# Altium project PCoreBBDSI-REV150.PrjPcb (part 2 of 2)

## Sheet 07) LCD CAM.SchDoc: LCD / CAM
size A3; Origin: Eagle; DrawnBy: T.Minas; DocumentNumber: 7; Revision: 1.50; SheetNumber: 7; SheetTotal: 10; Project: PicoCoreBBDSI
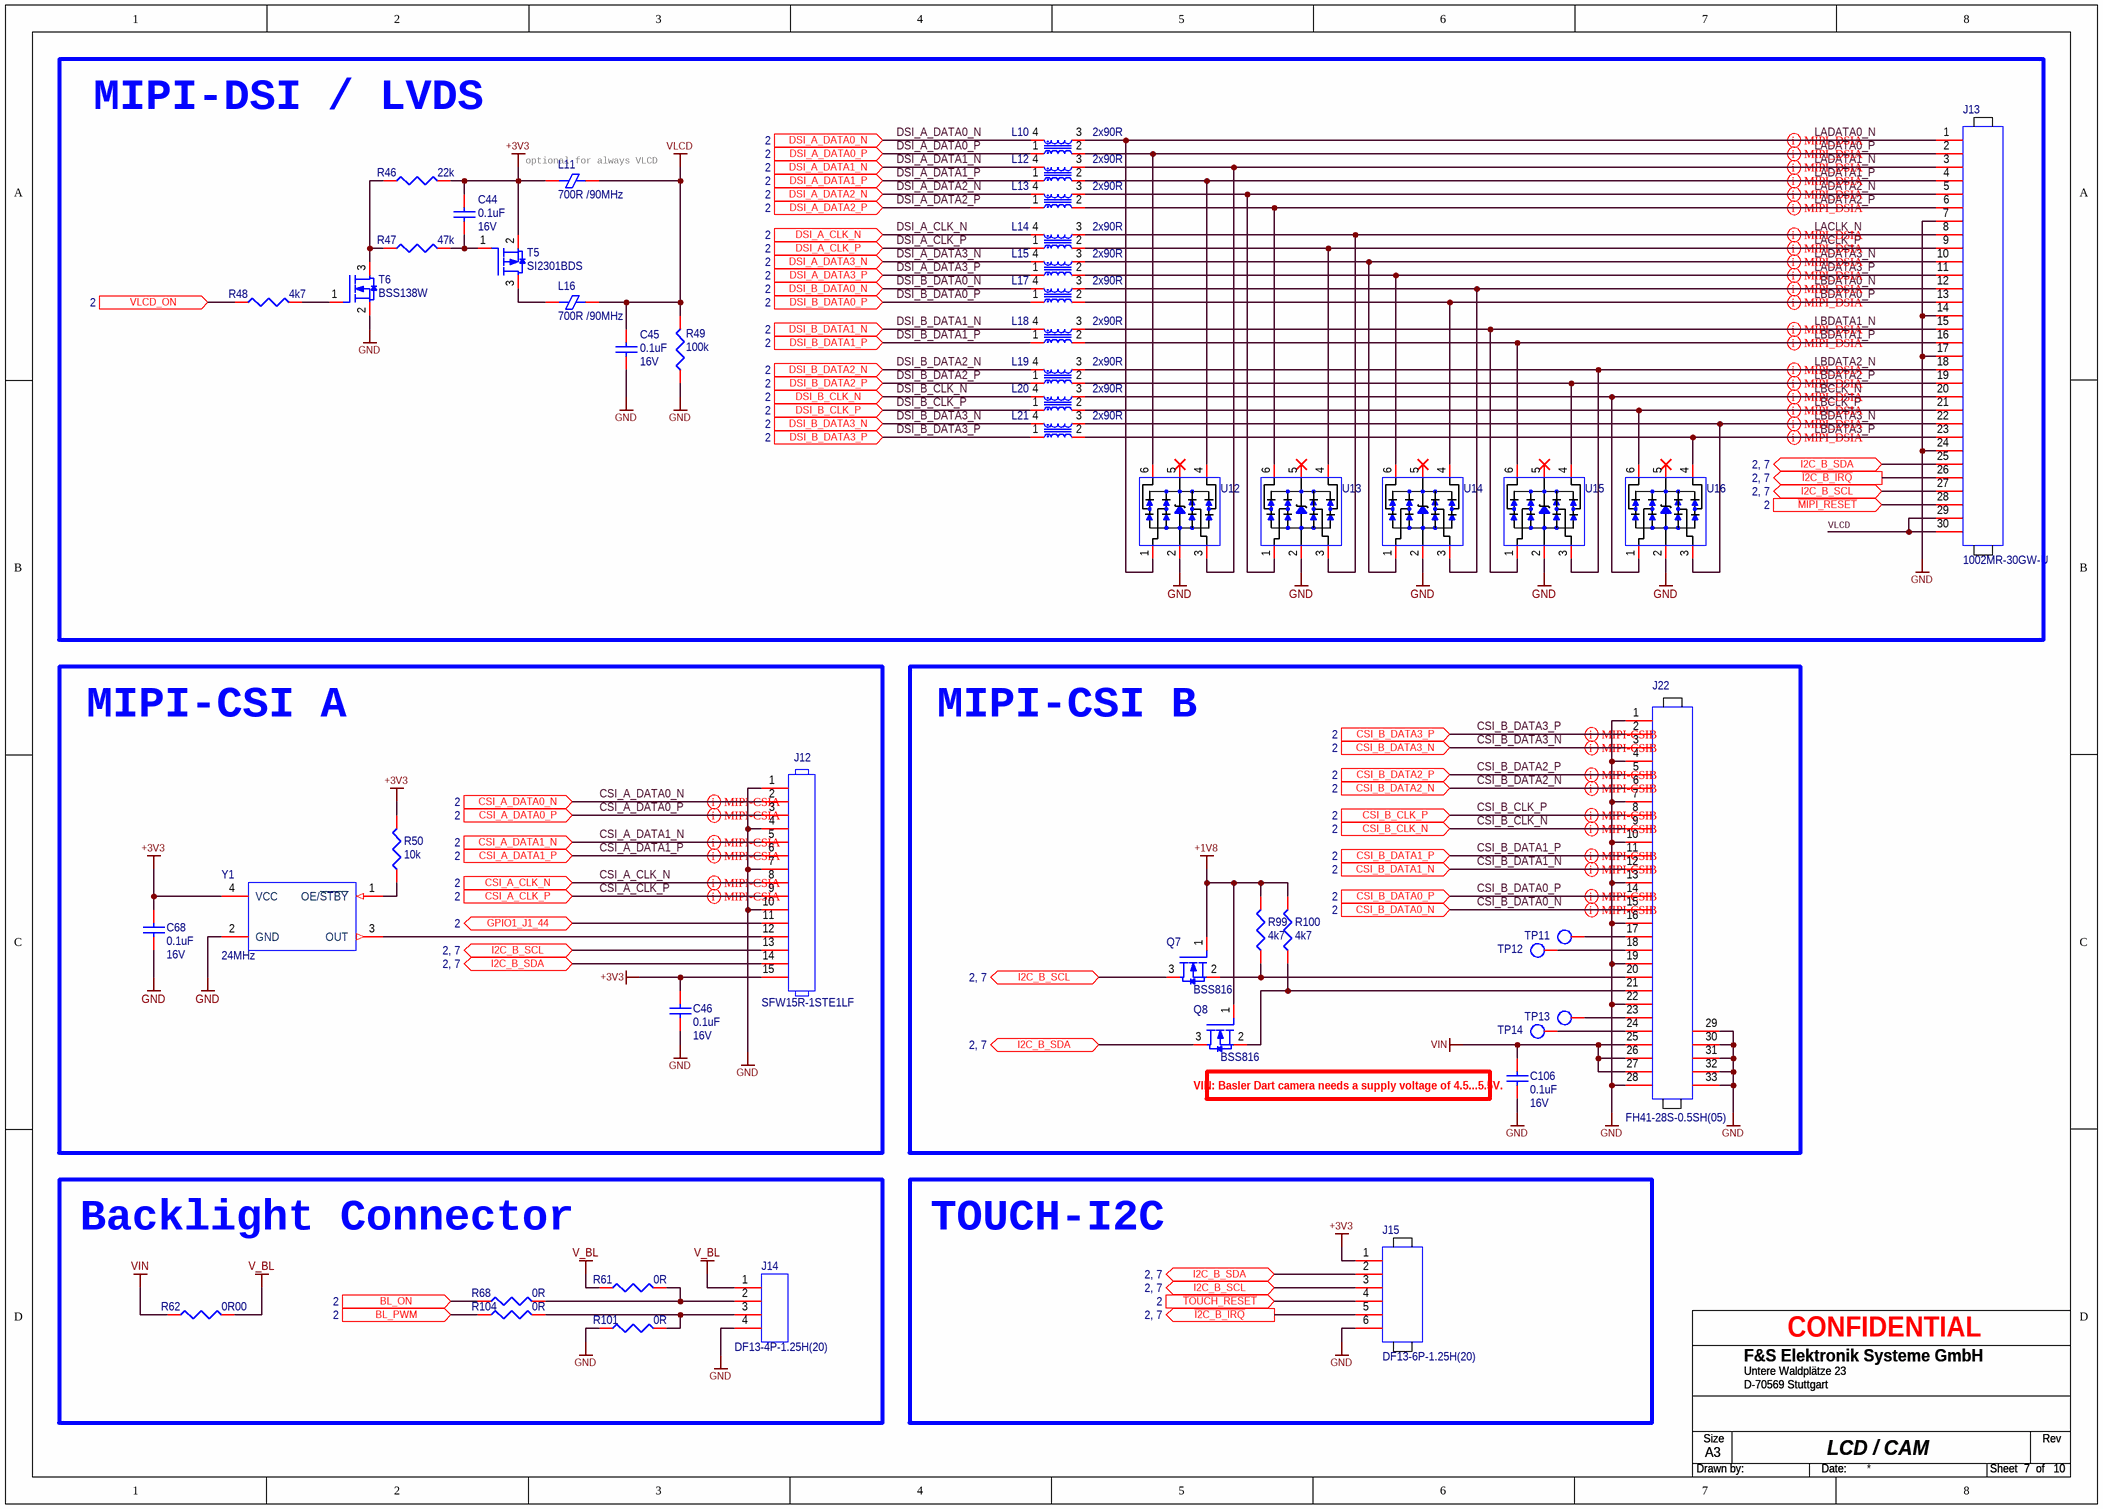
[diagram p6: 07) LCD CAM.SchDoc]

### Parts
C44  0.1uF  Voltage: 16V  [C0402]
C45  0.1uF  Voltage: 16V  [C0402]
C46  0.1uF  Voltage: 16V  [C0402]
C68  0.1uF  Voltage: 16V  [C0402]
C106  0.1uF  Voltage: 16V  [C0402]
J12  SFW15R-1STE1LF  [SFW15R-1STE1LF]
J13  1002MR-30GW-U  [JAE-30Pol.]
J14  DF13-4P-1.25H(20)  [DF13-4P-1.25H(20)]
J15  DF13-6P-1.25H(20)  [DF13-6P-1.25H(20)]
J22  FH41-28S-0.5SH(05)  [FH41-28S-0.5SH(05)]
L10  2x90R  [DLP11SN900HL2L]
L11  700R /90MHz  [L1206]
L12  2x90R  [DLP11SN900HL2L]
L13  2x90R  [DLP11SN900HL2L]
L14  2x90R  [DLP11SN900HL2L]
L15  2x90R  [DLP11SN900HL2L]
L16  700R /90MHz  [L1206]
L17  2x90R  [DLP11SN900HL2L]
L18  2x90R  [DLP11SN900HL2L]
L19  2x90R  [DLP11SN900HL2L]
L20  2x90R  [DLP11SN900HL2L]
L21  2x90R  [DLP11SN900HL2L]
Q7  BSS816  [SOT323 (SC70)]
Q8  BSS816  [SOT323 (SC70)]
R46  22k  [R0402]
R47  47k  [R0402]
R48  4k7  [R0402]
R49  100k  [R0402]
R50  10k  [R0402]
R61  0R  [R0402]
R62  0R00  [R0805]
R68  0R  [R0402]
R99  4k7  [R0402]
R100  4k7  [R0402]
R101  0R  [R0402]
R104  0R  [R0402]
T5  SI2301BDS  [SOT23-3]
T6  BSS138W  [SOT323 (SC70)]
TP11  TESTPOINT  [TP30SR34SMD]  (value not drawn)  (no BOM)
TP12  TESTPOINT  [TP30SR34SMD]  (value not drawn)  (no BOM)
TP13  TESTPOINT  [TP30SR34SMD]  (value not drawn)  (no BOM)
TP14  TESTPOINT  [TP30SR34SMD]  (value not drawn)  (no BOM)
U12  TVS Diode  [SOT23-6]  (value not drawn)
U13  TVS Diode  [SOT23-6]  (value not drawn)
U14  TVS Diode  [SOT23-6]  (value not drawn)
U15  TVS Diode  [SOT23-6]  (value not drawn)
U16  TVS Diode  [SOT23-6]  (value not drawn)
Y1  24MHz  [XTALD-4-302X205M]

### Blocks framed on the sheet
MIPI-DSI / LVDS: C44 C45 J13 L10-L21 R46-R49 T5 T6 U12-U16
MIPI-CSI A: C46 C68 J12 R50 Y1
MIPI-CSI B: C106 J22 Q7 Q8 R99 R100 TP11-TP14
Backlight Connector: J14 R61 R62 R68 R101 R104
TOUCH-I2C: J15

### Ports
BL_ON (in, see 2), BL_PWM (in, see 2), CSI_A_CLK_N (in, see 2), CSI_A_CLK_P (in, see 2), CSI_A_DATA0_N (in, see 2), CSI_A_DATA0_P (in, see 2), CSI_A_DATA1_N (in, see 2), CSI_A_DATA1_P (in, see 2), CSI_B_CLK_N (in, see 2), CSI_B_CLK_P (in, see 2), CSI_B_DATA0_N (in, see 2), CSI_B_DATA0_P (in, see 2), CSI_B_DATA1_N (in, see 2), CSI_B_DATA1_P (in, see 2), CSI_B_DATA2_N (in, see 2), CSI_B_DATA2_P (in, see 2), CSI_B_DATA3_N (in, see 2), CSI_B_DATA3_P (in, see 2), DSI_A_CLK_N (in, see 2), DSI_A_CLK_P (in, see 2), DSI_A_DATA0_N (in, see 2), DSI_A_DATA0_P (in, see 2), DSI_A_DATA1_N (in, see 2), DSI_A_DATA1_P (in, see 2), DSI_A_DATA2_N (in, see 2), DSI_A_DATA2_P (in, see 2), DSI_A_DATA3_N (in, see 2), DSI_A_DATA3_P (in, see 2), DSI_B_CLK_N (in, see 2), DSI_B_CLK_P (in, see 2), DSI_B_DATA0_N (in, see 2), DSI_B_DATA0_P (in, see 2), DSI_B_DATA1_N (in, see 2), DSI_B_DATA1_P (in, see 2), DSI_B_DATA2_N (in, see 2), DSI_B_DATA2_P (in, see 2), DSI_B_DATA3_N (in, see 2), DSI_B_DATA3_P (in, see 2), GPIO1_J1_44 (bidir, see 2), I2C_B_SCL (bidir, see 2, 7), I2C_B_SDA (bidir, see 2, 7), VLCD_ON (in, see 2), ~{I2C_B_IRQ} (out, see 2, 7), ~{MIPI_RESET} (in, see 2), ~{TOUCH_RESET} (in, see 2)

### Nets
+1V8: Q7.1 Q8.1 R99.2 R100.2
+3V3: C44.2 C46.2 C68.2 J12.15 J15.1 L11.2(FB2) R46.2 R50.2 T5.2 Y1.4(VCC)
GND: C45.1 C46.1 C68.1 C106.1 J12.1 J12.4 J12.7 J12.10 J13.7 J13.14 J13.17 J13.24 J14.4 J15.6 J22.1 J22.4 J22.7 J22.10 J22.13 J22.16 J22.19 J22.22 J22.28 J22.29 J22.30 J22.31 J22.32 J22.33 R49.1 R101.1 T6.2 U12.2(GND) U13.2(GND) U14.2(GND) U15.2(GND) U16.2(GND) Y1.2(GND)
V_BL: J14.1 R61.1 R62.2
VIN: C106.2 J22.25 J22.26 J22.27 R62.1
VLCD: C45.2 J13.29 J13.30 L11.1(FB1) L16.1(FB1) R49.2
CSI_A_CLK_N: J12.8 ; port CSI_A_CLK_N
CSI_A_CLK_P: J12.9 ; port CSI_A_CLK_P
CSI_A_DATA0_N: J12.2 ; port CSI_A_DATA0_N
CSI_A_DATA0_P: J12.3 ; port CSI_A_DATA0_P
CSI_A_DATA1_N: J12.5 ; port CSI_A_DATA1_N
CSI_A_DATA1_P: J12.6 ; port CSI_A_DATA1_P
CSI_B_CLK_N: J22.9 ; port CSI_B_CLK_N
CSI_B_CLK_P: J22.8 ; port CSI_B_CLK_P
CSI_B_DATA0_N: J22.15 ; port CSI_B_DATA0_N
CSI_B_DATA0_P: J22.14 ; port CSI_B_DATA0_P
CSI_B_DATA1_N: J22.12 ; port CSI_B_DATA1_N
CSI_B_DATA1_P: J22.11 ; port CSI_B_DATA1_P
CSI_B_DATA2_N: J22.6 ; port CSI_B_DATA2_N
CSI_B_DATA2_P: J22.5 ; port CSI_B_DATA2_P
CSI_B_DATA3_N: J22.3 ; port CSI_B_DATA3_N
CSI_B_DATA3_P: J22.2 ; port CSI_B_DATA3_P
DSI_A_CLK_N: L14.4 ; port DSI_A_CLK_N
DSI_A_CLK_P: L14.1 ; port DSI_A_CLK_P
DSI_A_DATA0_N: L10.4 ; port DSI_A_DATA0_N
DSI_A_DATA0_P: L10.1 ; port DSI_A_DATA0_P
DSI_A_DATA1_N: L12.4 ; port DSI_A_DATA1_N
DSI_A_DATA1_P: L12.1 ; port DSI_A_DATA1_P
DSI_A_DATA2_N: L13.4 ; port DSI_A_DATA2_N
DSI_A_DATA2_P: L13.1 ; port DSI_A_DATA2_P
DSI_A_DATA3_N: L15.4 ; port DSI_A_DATA3_N
DSI_A_DATA3_P: L15.1 ; port DSI_A_DATA3_P
DSI_B_CLK_N: L20.4 ; port DSI_B_CLK_N
DSI_B_CLK_P: L20.1 ; port DSI_B_CLK_P
DSI_B_DATA0_N: L17.4 ; port DSI_B_DATA0_N
DSI_B_DATA0_P: L17.1 ; port DSI_B_DATA0_P
DSI_B_DATA1_N: L18.4 ; port DSI_B_DATA1_N
DSI_B_DATA1_P: L18.1 ; port DSI_B_DATA1_P
DSI_B_DATA2_N: L19.4 ; port DSI_B_DATA2_N
DSI_B_DATA2_P: L19.1 ; port DSI_B_DATA2_P
DSI_B_DATA3_N: L21.4 ; port DSI_B_DATA3_N
DSI_B_DATA3_P: L21.1 ; port DSI_B_DATA3_P
GPIO_J1_44: J12.11 ; port GPIO1_J1_44
I2C_B_SCL: J12.13 J13.27 J15.3 Q7.3 ; port I2C_B_SCL
I2C_B_SDA: J12.14 J13.25 J15.2 Q8.3 ; port I2C_B_SDA
~{I2C_B_IRQ}: J13.26 J15.5 ; port ~{I2C_B_IRQ}
LACLK_N: J13.8 L14.3 U13.3(I/O3)
LACLK_P: J13.9 L14.2 U13.4(I/O4)
LADATA0_N: J13.1 L10.3 U12.1(I/O1)
LADATA0_P: J13.2 L10.2 U12.6(I/O6)
LADATA1_N: J13.3 L12.3 U12.3(I/O3)
LADATA1_P: J13.4 L12.2 U12.4(I/O4)
LADATA2_N: J13.5 L13.3 U13.1(I/O1)
LADATA2_P: J13.6 L13.2 U13.6(I/O6)
LADATA3_N: J13.10 L15.3 U14.1(I/O1)
LADATA3_P: J13.11 L15.2 U14.6(I/O6)
LBCLK_N: J13.20 L20.3 U16.1(I/O1)
LBCLK_P: J13.21 L20.2 U16.6(I/O6)
LBDATA0_N: J13.12 L17.3 U14.3(I/O3)
LBDATA0_P: J13.13 L17.2 U14.4(I/O4)
LBDATA1_N: J13.15 L18.3 U15.1(I/O1)
LBDATA1_P: J13.16 L18.2 U15.6(I/O6)
LBDATA2_N: J13.18 L19.3 U15.3(I/O3)
LBDATA2_P: J13.19 L19.2 U15.4(I/O4)
LBDATA3_N: J13.22 L21.3 U16.3(I/O3)
LBDATA3_P: J13.23 L21.2 U16.4(I/O4)
NetC44_1: C44.1 R47.2 T5.1
NetJ1_2: J15.4 ; port ~{TOUCH_RESET}
NetJ1_7: J13.28 ; port ~{MIPI_RESET}
NetJ1_9: R68.1 ; port BL_ON
NetJ1_11: R104.1 ; port BL_PWM
NetJ1_13: R48.1 ; port VLCD_ON
NetJ12_12: J12.12 Y1.3(OUT)
NetJ14_2: J14.2 R61.2 R68.2
NetJ14_3: J14.3 R101.2 R104.2
NetJ22_17: J22.17 TP11.1(TP)
NetJ22_18: J22.18 TP12.1(TP)
NetJ22_20: J22.20 Q7.2 R99.1
NetJ22_21: J22.21 Q8.2 R100.1
NetJ22_23: J22.23 TP13.1(TP)
NetJ22_24: J22.24 TP14.1(TP)
NetL16_2: L16.2(FB2) T5.3
NetR46_1: R46.1 R47.1 T6.3
NetR48_2: R48.2 T6.1
NetR50_1: R50.1 Y1.1(OE/~{STBY})

Not connected (* = marked no-connect by the designer): U12 5(VCC)*; U13 5(VCC)*; U14 5(VCC)*; U15 5(VCC)*; U16 5(VCC)*

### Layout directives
differential pair; differential pair class MIPI-DSI: LACLK_N, LACLK_P, LADATA0_N, LADATA0_P, LADATA1_N, LADATA1_P, LADATA2_N, LADATA2_P, LADATA3_N, LADATA3_P, LBCLK_N, LBCLK_P, LBDATA0_N, LBDATA0_P, LBDATA1_N, LBDATA1_P, LBDATA2_N, LBDATA2_P, LBDATA3_N, LBDATA3_P
differential pair; differential pair class MIPI-CSI_A: CSI_A_CLK_N, CSI_A_CLK_P, CSI_A_DATA0_N, CSI_A_DATA0_P, CSI_A_DATA1_N, CSI_A_DATA1_P
differential pair; differential pair class MIPI-CSI_B: CSI_B_CLK_N, CSI_B_CLK_P, CSI_B_DATA0_N, CSI_B_DATA0_P, CSI_B_DATA1_N, CSI_B_DATA1_P, CSI_B_DATA2_N, CSI_B_DATA2_P, CSI_B_DATA3_N, CSI_B_DATA3_P

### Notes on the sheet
- (near L11) optional for always VLCD
- (near C106) VIN: Basler Dart camera needs a supply voltage of 4.5...5.5V.

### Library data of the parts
C44-C46 C68 C106 = 380: 100nF  10%  16V  X7R  0402; FS-EDV-Nummer: B.CKV.42; Class: Capacitor Ceramic; Tolerance: 10; ID: 380
J12 = 2726: FPC 15 pol. 1,0mm side / SMT; ID: 2726; Class: Connector; FS-EDV-Nummer: B.MBU.1R15PL.1
J13 = 2728: FPC 30 pol. 1.00mm side entry SMT; FS-EDV-Nummer: B.MBU.1R30PL.3; Class: Connector; ID: 2728
J14 = 2721: Stiftl. 4 pol. crimpable  liegend RM:1.25; FS-EDV-Nummer: B.MST.1R4PL.9; Class: Connector; ID: 2721
J15 = 2720: Stiftl. 6 pol. crimpable  liegend RM:1.25; FS-EDV-Nummer: B.MST.1R6PL.2; Class: Connector; ID: 2720
J22 = 2781: ID: 2781; Class: Connector; FS-EDV-Nummer: B.MBU.1R28PL.2
L10 L12-L15 L17-L21 = 2731: Common Mode Choke  20%  2x 90 Ohm  0504; FS-EDV-Nummer: B.EMVFER.13; Voltage: 5V; Power: 150mA; ID: 2731
L11 L16 = 2705: WE-CBF  25%  700R  90MHz  EMI  1206; Part Number: 74279218; FS-EDV-Nummer: B.EMVFER.5; Class: Ferit; ID: 2705
Q7 Q8 = 2772: MOSFET N-CH 20V 1.4A SOT323(SC-70); ID: 2772; FS-EDV-Nummer: B.TPMFN.12; Power: 0,5W
R46 = 179: 22k 1/16W 1% SMD 0402; FS-EDV-Nummer: B.R22K0.1; Tolerance: 1; ID: 179
R47 = 186: 47k 1/16W 1% SMD 0402; FS-EDV-Nummer: B.R47K0.1; Tolerance: 1; ID: 186
R48 = 184: 4k7 1/16W max 5% SMD 0402; FS-EDV-Nummer: B.R4K7.3; Tolerance: 5; ID: 184
R49 = 177: 100k 1/16W 1% SMD 0402; FS-EDV-Nummer: B.R100K.3; Tolerance: 1; ID: 177
R50 = 170: 10k 1/16W 1% SMD 0402; ID: 170; FS-EDV-Nummer: B.R10K.3; Tolerance: 1
R61 R68 R101 R104 = 173: 0R 1/16W max 5% SMD 0402; ID: 173; FS-EDV-Nummer: B.R0R0.1; Tolerance: 5
R62 = 6: 0R00 0,125W max 5% SMD 0805; ID: 6; FS-EDV-Nummer: B.R000.2.S; Power: 0,125W; Tolerance: 5
R99 R100 = 184: 4k7 1/16W max 5% SMD 0402; ID: 184; FS-EDV-Nummer: B.R4K7.3; Tolerance: 5
T5 = 2691: Si2301BDS SOT-23 P-Kanal; FS-EDV-Nummer: B.TPMFP.2.S; Class: MOSFET; ID: 2691
T6 = 2689: BSS138W SOT323(SC-70) N-Kanal; FS-EDV-Nummer: B.TPMFN.10; Class: MOSFET; ID: 2689
U12-U16 = 2710: 4 Channel  5,5V  TVS Diode Array  SOT-23-6; Part Number: AOZ8904CIL; CLASS: ESD; FS-EDV-Nummer: B.EMVSUP.2; ID: 2710
Y1 = 2732: 24MHz SMD 3,2x2,5mm; Part Number: ASEMB-24.000MHZ-LC-T; ID: 2732; Class: Crystal Oscillator; FS-EDV-Nummer: B.OSZ.15; Power: <10mA; Tolerance: 10ppm

## Sheet 08) Ethernet Can.SchDoc: Ethernet / CAN
size A3; Origin: Eagle; DrawnBy: T.Minas; DocumentNumber: 8; Revision: 1.50; SheetNumber: 8; SheetTotal: 10; Project: PicoCoreBBDSI
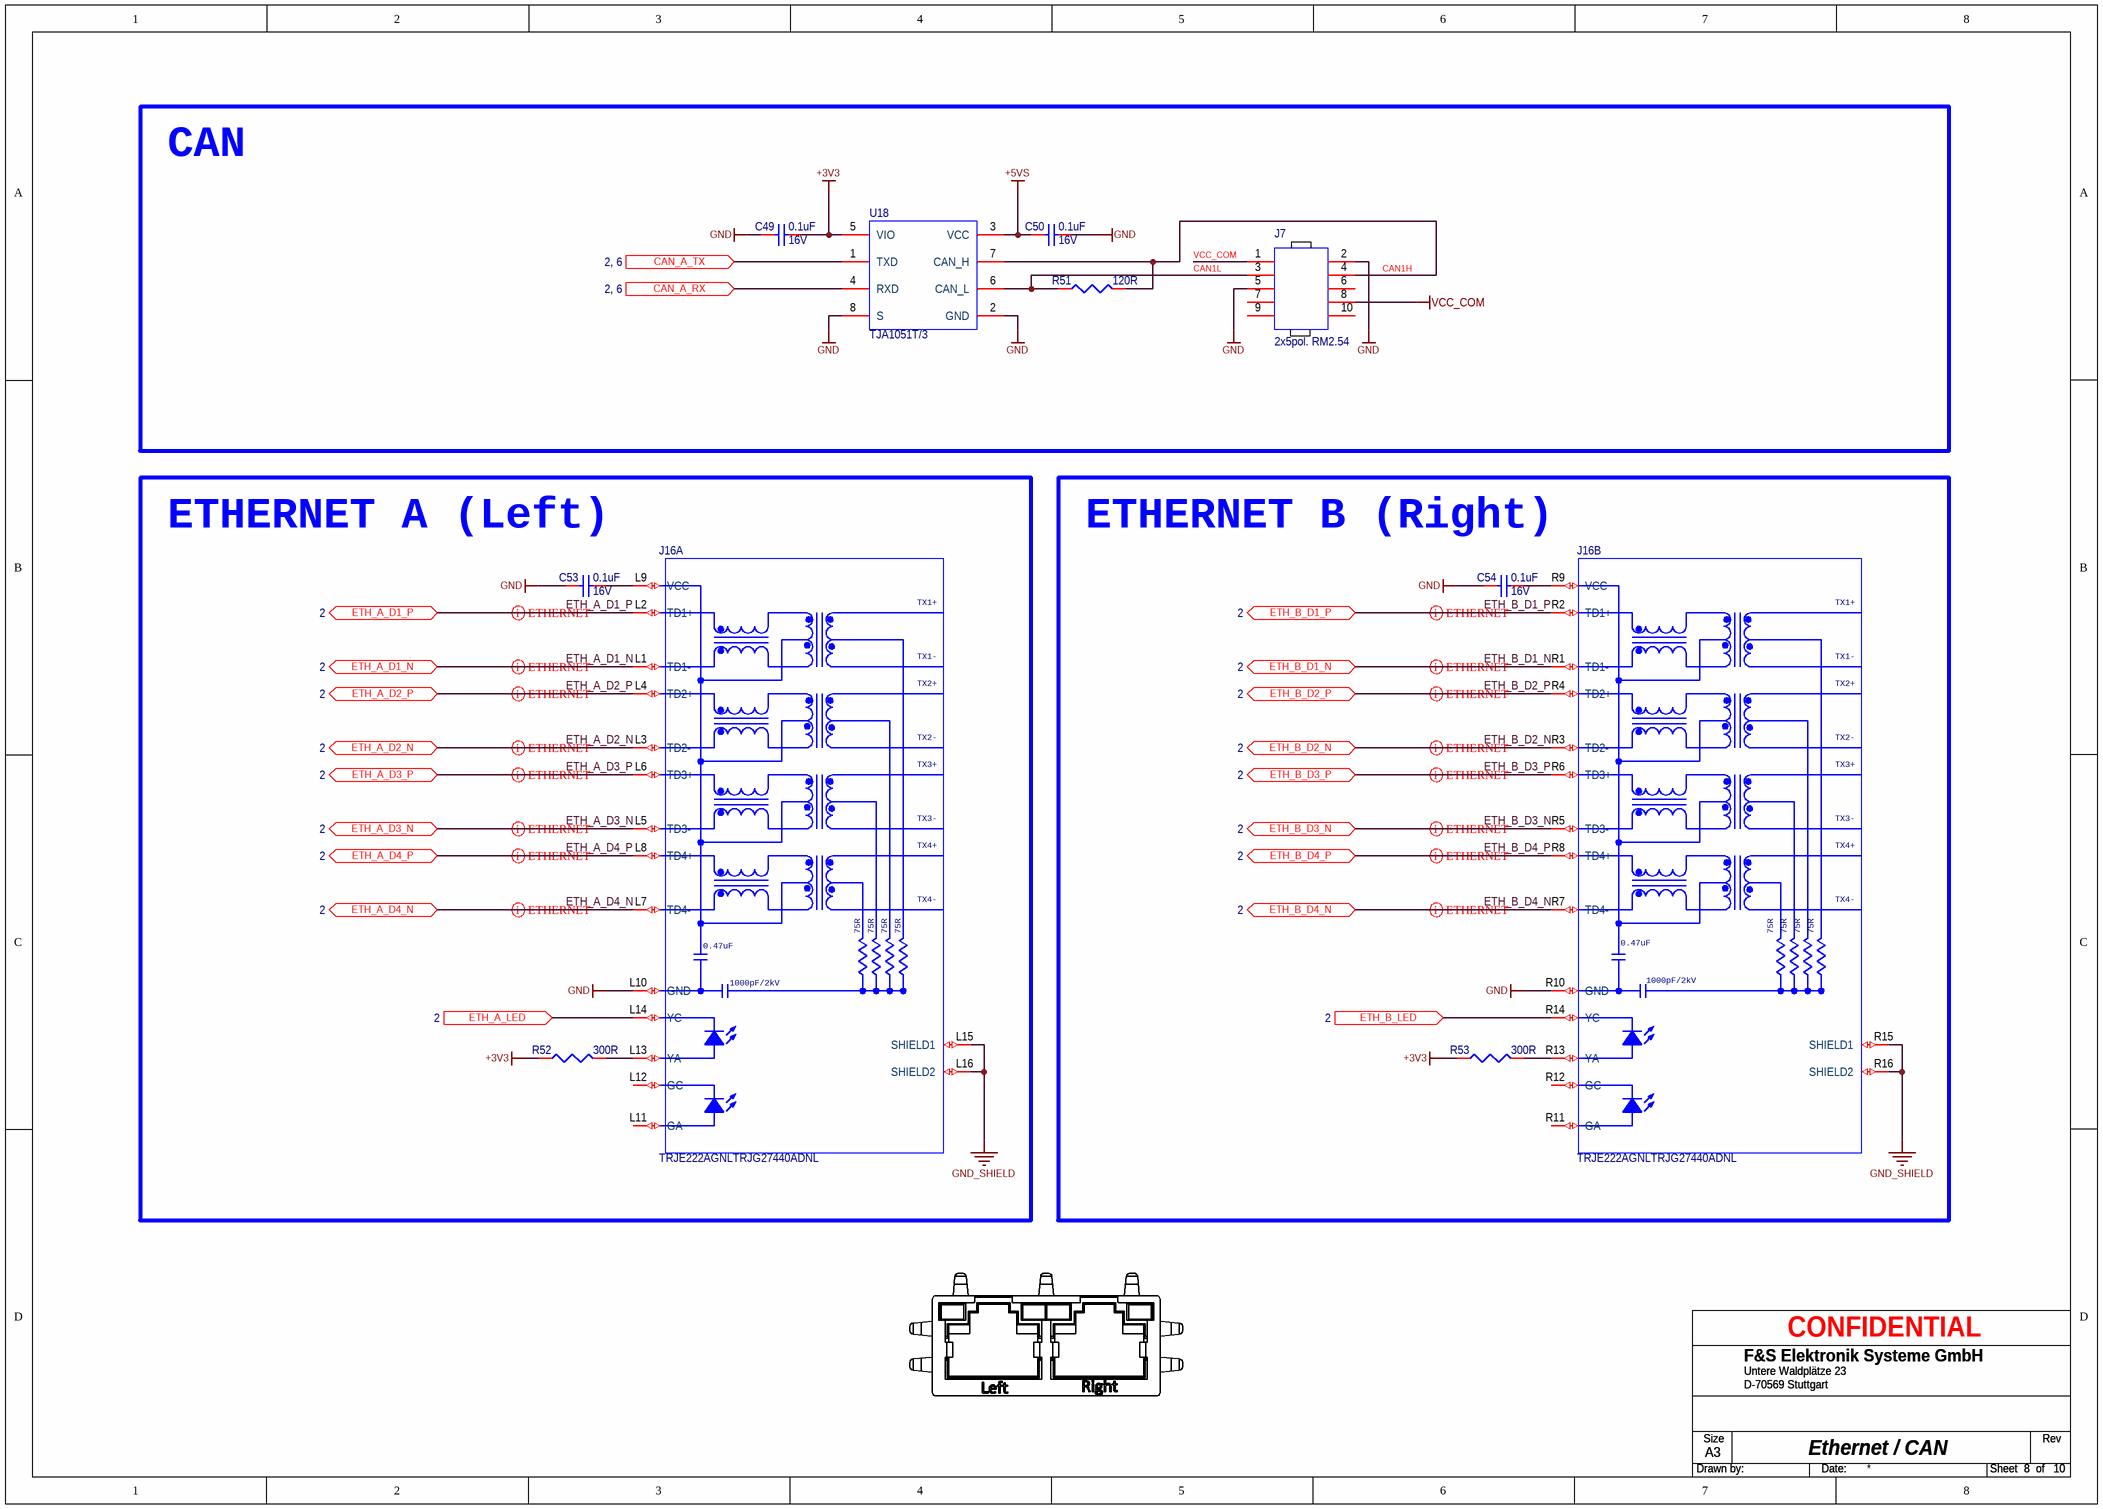
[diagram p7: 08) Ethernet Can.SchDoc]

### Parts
C49  0.1uF  Voltage: 16V  [C0402]
C50  0.1uF  Voltage: 16V  [C0402]
C53  0.1uF  Voltage: 16V  [C0402]
C54  0.1uF  Voltage: 16V  [C0402]
J7  2x5pol. RM2.54  [COM-5X2]
J16  TRJE222AGNLTRJG27440ADNL  [TRJG27440ADNL]  (parts A,B of 2)
R51  120R  [R0402]
R52  300R  [R0402]
R53  300R  [R0402]
U18  TJA1051T/3  [SOIC-8_M]

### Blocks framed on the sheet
CAN: C49 C50 J7 R51 U18
ETHERNET A (Left): C53 J16 R52
ETHERNET B (Right): C54 J16 R53

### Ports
CAN_A_RX (in, see 2, 6), CAN_A_TX (in, see 2, 6), ETH_A_D1_N (bidir, see 2), ETH_A_D1_P (bidir, see 2), ETH_A_D2_N (bidir, see 2), ETH_A_D2_P (bidir, see 2), ETH_A_D3_N (bidir, see 2), ETH_A_D3_P (bidir, see 2), ETH_A_D4_N (bidir, see 2), ETH_A_D4_P (bidir, see 2), ETH_A_LED (in, see 2), ETH_B_D1_N (bidir, see 2), ETH_B_D1_P (bidir, see 2), ETH_B_D2_N (bidir, see 2), ETH_B_D2_P (bidir, see 2), ETH_B_D3_N (bidir, see 2), ETH_B_D3_P (bidir, see 2), ETH_B_D4_N (bidir, see 2), ETH_B_D4_P (bidir, see 2), ETH_B_LED (in, see 2)

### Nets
+3V3: C49.2 R52.1 R53.1 U18.5(VIO)
+5VS: C50.1 U18.3(VCC)
GND: C49.1 C50.2 C53.1 C54.1 J7.2 J7.5 J16.L10(GND) J16.R10(GND) U18.2(GND) U18.8(S)
GND_SHIELD: J16.L15(SHIELD1) J16.L16(SHIELD2) J16.R15(SHIELD1) J16.R16(SHIELD2)
VCC_COM: J7.1 J7.8
CAN1H: J7.4 R51.2 U18.7(CAN_H)
CAN1L: J7.3 R51.1 U18.6(CAN_L)
ETH_A_D1_N: J16.L1(TD1-) ; port ETH_A_D1_N
ETH_A_D1_P: J16.L2(TD1+) ; port ETH_A_D1_P
ETH_A_D2_N: J16.L3(TD2-) ; port ETH_A_D2_N
ETH_A_D2_P: J16.L4(TD2+) ; port ETH_A_D2_P
ETH_A_D3_N: J16.L5(TD3-) ; port ETH_A_D3_N
ETH_A_D3_P: J16.L6(TD3+) ; port ETH_A_D3_P
ETH_A_D4_N: J16.L7(TD4-) ; port ETH_A_D4_N
ETH_A_D4_P: J16.L8(TD4+) ; port ETH_A_D4_P
ETH_B_D1_N: J16.R1(TD1-) ; port ETH_B_D1_N
ETH_B_D1_P: J16.R2(TD1+) ; port ETH_B_D1_P
ETH_B_D2_N: J16.R3(TD2-) ; port ETH_B_D2_N
ETH_B_D2_P: J16.R4(TD2+) ; port ETH_B_D2_P
ETH_B_D3_N: J16.R5(TD3-) ; port ETH_B_D3_N
ETH_B_D3_P: J16.R6(TD3+) ; port ETH_B_D3_P
ETH_B_D4_N: J16.R7(TD4-) ; port ETH_B_D4_N
ETH_B_D4_P: J16.R8(TD4+) ; port ETH_B_D4_P
NetC53_2: C53.2 J16.L9(VCC)
NetC54_2: C54.2 J16.R9(VCC)
NetJ1_10: U18.4(RXD) ; port CAN_A_RX
NetJ1_12: U18.1(TXD) ; port CAN_A_TX
NetJ2_17: J16.L14(YC) ; port ETH_A_LED
NetJ2_21: J16.R14(YC) ; port ETH_B_LED
NetJ16_L13: J16.L13(YA) R52.2
NetJ16_R13: J16.R13(YA) R53.2

Not connected (* = marked no-connect by the designer): J7 6 7 9 10; J16 L11(GA) L12(GC) R11(GA) R12(GC)

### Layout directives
differential pair; differential pair class ETHERNET: ETH_A_D1_N, ETH_A_D1_P, ETH_A_D2_N, ETH_A_D2_P, ETH_A_D3_N, ETH_A_D3_P, ETH_A_D4_N, ETH_A_D4_P, ETH_B_D1_N, ETH_B_D1_P, ETH_B_D2_N, ETH_B_D2_P, ETH_B_D3_N, ETH_B_D3_P, ETH_B_D4_N, ETH_B_D4_P

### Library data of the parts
C49 C50 C53 C54 = 380: as C44-C46 on sheet 07) LCD CAM
J7 = 2714: Stiftl. mit Wanne 10 pol. 2 reih.  steh.; FS-EDV-Nummer: B.MST.2R10PS.4; Class: Connector; ID: 2714; THT: X
J16 = 2715: RJ45 / 2x1 / 1G / LED(y/g) / liegend / Tab Up / THT; ID: 2715; Class: Connector; FS-EDV-Nummer: B.MBU.2R8PL.1; THT: X
R51 = 309: 120R 1/16W 1% SMD 0402; FS-EDV-Nummer: B.R120R.2; Tolerance: 1; ID: 309
R52 R53 = 190: 300R 1/16W 1% SMD 0402; FS-EDV-Nummer: B.R300R.1; Tolerance: 1; ID: 190
U18 = 1269: FS-EDV-Nummer: B.ICIF.94; Voltage: 3…5V; Class: IC; ID: 1269

## Sheet 09) mPCIe.SchDoc: mPCIe
size A3; Origin: Eagle; DrawnBy: T.Minas; DocumentNumber: 9; Revision: 1.50; SheetNumber: 9; SheetTotal: 10; Project: PicoCoreBBDSI
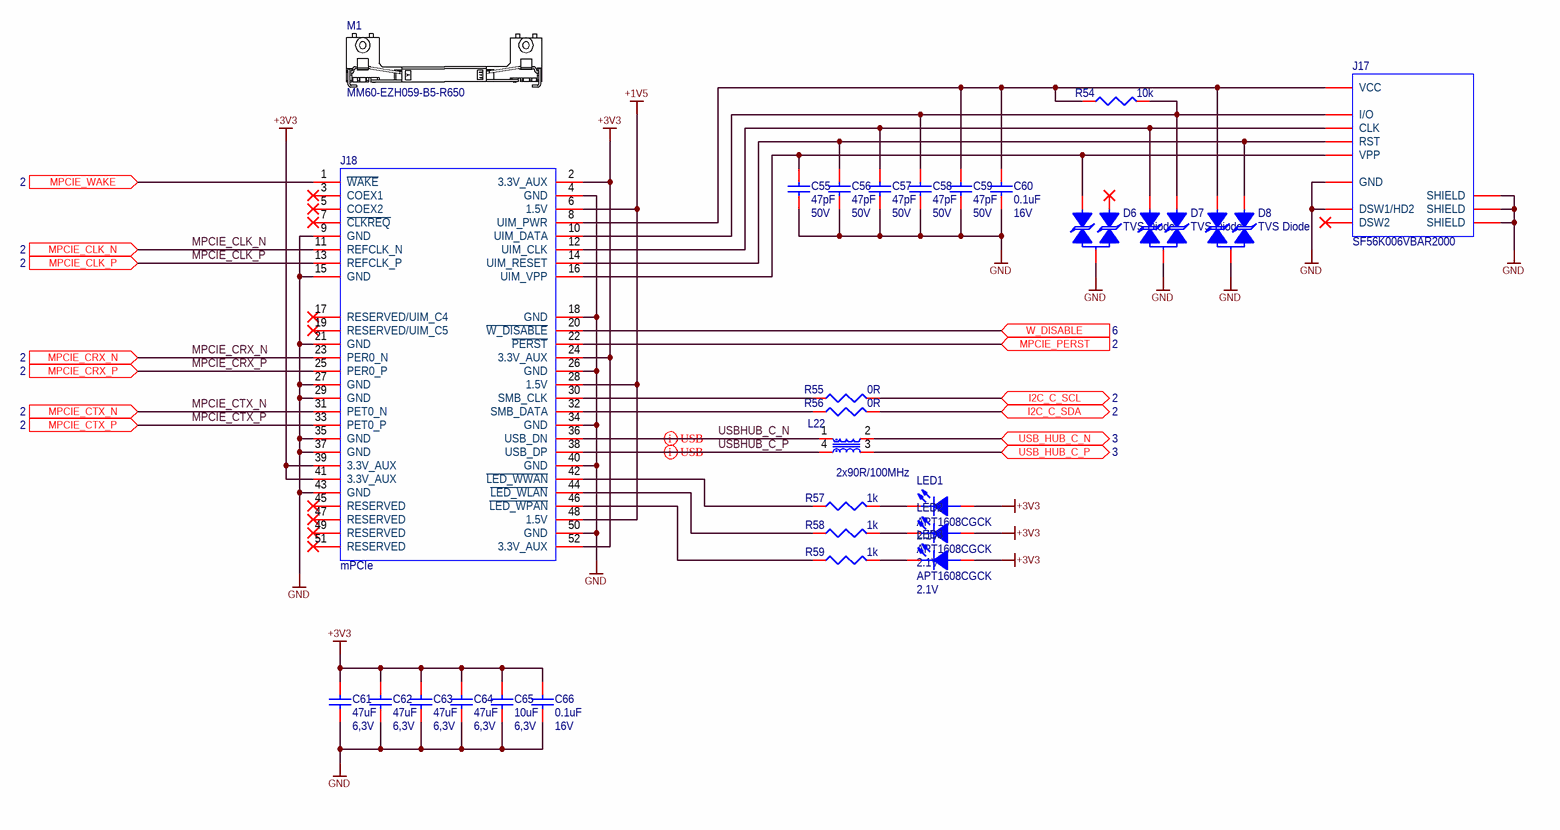
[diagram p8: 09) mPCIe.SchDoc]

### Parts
C55  47pF  Voltage: 50V  [C0402]
C56  47pF  Voltage: 50V  [C0402]
C57  47pF  Voltage: 50V  [C0402]
C58  47pF  Voltage: 50V  [C0402]
C59  47pF  Voltage: 50V  [C0402]
C60  0.1uF  Voltage: 16V  [C0402]
C61  47uF  Voltage: 6,3V  [C0805]
C62  47uF  Voltage: 6,3V  [C0805]
C63  47uF  Voltage: 6,3V  [C0805]
C64  47uF  Voltage: 6,3V  [C0805]
C65  10uF  Voltage: 6,3V  [C0603]
C66  0.1uF  Voltage: 16V  [C0402]
D6  TVS Diode  [SOT23-3]
D7  TVS Diode  [SOT23-3]
D8  TVS Diode  [SOT23-3]
J17  SF56K006VBAR2000  [SF56K006VBAR2000]
J18  mPCIe  [MM60-52B1-E1-R650]
L22  2x90R/100MHz  [USBSHOCK4-0805-12]
LED1  APT1608CGCK  Voltage: 2.1V  [LED0603]
LED2  APT1608CGCK  Voltage: 2.1V  [LED0603]
LED3  APT1608CGCK  Voltage: 2.1V  [LED0603]
M1  MM60-EZH059-B5-R650  [MM60-EZH059-B5-R650]
R54  10k  [R0402]
R55  0R  [R0402]
R56  0R  [R0402]
R57  1k  [R0402]
R58  1k  [R0402]
R59  1k  [R0402]

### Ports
I2C_C_SCL (bidir, see 2), I2C_C_SDA (bidir, see 2), MPCIE_CLK_N (in, see 2), MPCIE_CLK_P (in, see 2), MPCIE_CRX_N (in, see 2), MPCIE_CRX_P (in, see 2), MPCIE_CTX_N (in, see 2), MPCIE_CTX_P (in, see 2), MPCIE_PERST (in, see 2), MPCIE_WAKE (in, see 2), USB_HUB_C_N (bidir, see 3), USB_HUB_C_P (bidir, see 3), W_DISABLE (in, see 6)

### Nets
+1V5: J18.6(1.5V) J18.28(1.5V) J18.48(1.5V)
+3V3: C61.2 C62.2 C63.2 C64.2 C65.2 C66.2 J18.2(3.3V_AUX) J18.24(3.3V_AUX) J18.39(3.3V_AUX) J18.41(3.3V_AUX) J18.52(3.3V_AUX) LED1.2(AN_GRN) LED2.2(AN_GRN) LED3.2(AN_GRN)
GND: C55.1 C56.1 C57.1 C58.1 C59.1 C60.1 C61.1 C62.1 C63.1 C64.1 C65.1 C66.1 D6.3 D7.3 D8.3 J17.C5(GND) J17.HD1(SHIELD) J17.HD2DSW1(DSW1/HD2) J17.HD3(SHIELD) J17.HD4(SHIELD) J18.4(GND) J18.9(GND) J18.15(GND) J18.18(GND) J18.21(GND) J18.26(GND) J18.27(GND) J18.29(GND) J18.34(GND) J18.35(GND) J18.37(GND) J18.40(GND) J18.43(GND) J18.50(GND)
MPCIE_CLK_N: J18.11(REFCLK_N) ; port MPCIE_CLK_N
MPCIE_CLK_P: J18.13(REFCLK_P) ; port MPCIE_CLK_P
MPCIE_CRX_N: J18.23(PER0_N) ; port MPCIE_CRX_N
MPCIE_CRX_P: J18.25(PER0_P) ; port MPCIE_CRX_P
MPCIE_CTX_N: J18.31(PET0_N) ; port MPCIE_CTX_N
MPCIE_CTX_P: J18.33(PET0_P) ; port MPCIE_CTX_P
USBDM3_N: L22.2 ; port USB_HUB_C_N
USBDM3_P: L22.3 ; port USB_HUB_C_P
USBHUB_C_N: J18.36(USB_DN) L22.1
USBHUB_C_P: J18.38(USB_DP) L22.4
NetC55_2: C55.2 D6.2 J17.C6(VPP) J18.16(UIM_VPP)
NetC56_2: C56.2 D8.1 J17.C2(RST) J18.14(UIM_RESET)
NetC57_2: C57.2 D7.2 J17.C3(CLK) J18.12(UIM_CLK)
NetC58_2: C58.2 D7.1 J17.C7(I/O) J18.10(UIM_DATA) R54.2
NetC59_2: C59.2 C60.2 D8.2 J17.C1(VCC) J18.8(UIM_PWR) R54.1
NetJ1_40: R55.2 ; port I2C_C_SCL
NetJ1_42: R56.2 ; port I2C_C_SDA
NetJ1_95: J18.22(~{PERST}) ; port MPCIE_PERST
NetJ1_97: J18.1(~{WAKE}) ; port MPCIE_WAKE
NetJ18_20: J18.20(~{W_DISABLE}) ; port W_DISABLE
NetJ18_30: J18.30(SMB_CLK) R55.1
NetJ18_32: J18.32(SMB_DATA) R56.1
NetJ18_42: J18.42(~{LED_WWAN}) R57.1
NetJ18_44: J18.44(~{LED_WLAN}) R58.1
NetJ18_46: J18.46(~{LED_WPAN}) R59.1
NetLED1_1: LED1.1(CAT_GRN) R57.2
NetLED2_1: LED2.1(CAT_GRN) R58.2
NetLED3_1: LED3.1(CAT_GRN) R59.2

Not connected (* = marked no-connect by the designer): D6 1*; J17 DSW2*; J18 3(COEX1)* 5(COEX2)* 7(~{CLKREQ})* 17(RESERVED/UIM_C4)* 19(RESERVED/UIM_C5)* 45(RESERVED)* 47(RESERVED)* 49(RESERVED)* 51(RESERVED)*

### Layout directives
differential pair; differential pair class USB: USBHUB_C_N, USBHUB_C_P

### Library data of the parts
C55-C59 = 390: 47pF  10%  50V  C0G/NP0  0402; FS-EDV-Nummer: B.CKV.73; Class: Capacitor Ceramic; Tolerance: 10; ID: 390
C60 C66 = 380: as C44-C46 on sheet 07) LCD CAM
C61-C64 = 442: 47uF  20%  6,3V  X5R  0805; FS-EDV-Nummer: B.CKV.69; Class: Capacitor Ceramic; Tolerance: 20; ID: 442
C65 = 406: 10uF  20%  6,3V  X5R  0603; FS-EDV-Nummer: B.CKV.46; Class: Capacitor Ceramic; Tolerance: 20; ID: 406
D6-D8 = 2709: 2 Channel ESD Protection TVS Diode SOT-23-3; Part Number: PGB102ST23WR; Number devices in Package: 1; OriginalSymbolOrigin: (0,0); FS-EDV-Nummer: B.EMVSUP.1; ID: 2709
J17 = 2727: Micro SIM Steckverbinder push-push; ID: 2727; Class: Connector; FS-EDV-Nummer: B.MST.1R6PL.3
J18 = 2713: mini PCIe SMD 52 pin; FS-EDV-Nummer: B.MST.2R52PL.1; Class: Connector; ID: 2713
L22 = 2698: Common Mode Choke  20%  2x 90 Ohm  0805; FS-EDV-Nummer: B.EMVFER.11; Power: 400mA; ID: 2698
LED1-LED3 = 2744: LED  Green  View 120°  0603; ID: 2744; FS-EDV-Nummer: B.DLED.11; Power: 0.02A
M1 = 2734: MINI EXPRESS CARD LATCH SMD; FS-EDV-Nummer: B.MST.VR.3; ID: 2734
R54 = 170: 10k 1/16W 1% SMD 0402; FS-EDV-Nummer: B.R10K.3; Tolerance: 1; ID: 170
R55 R56 = 173: 0R 1/16W max 5% SMD 0402; FS-EDV-Nummer: B.R0R0.1; Tolerance: 5; ID: 173
R57-R59 = 166: 1k 1/16W 1% SMD 0402; FS-EDV-Nummer: B.R1K00.1; Tolerance: 1; ID: 166

## Sheet 10) DCDC.SchDoc: DC / DC
size A3; Origin: Eagle; DrawnBy: T.Minas; DocumentNumber: 10; Revision: 1.50; SheetNumber: 10; SheetTotal: 10; Project: PicoCoreBBDSI
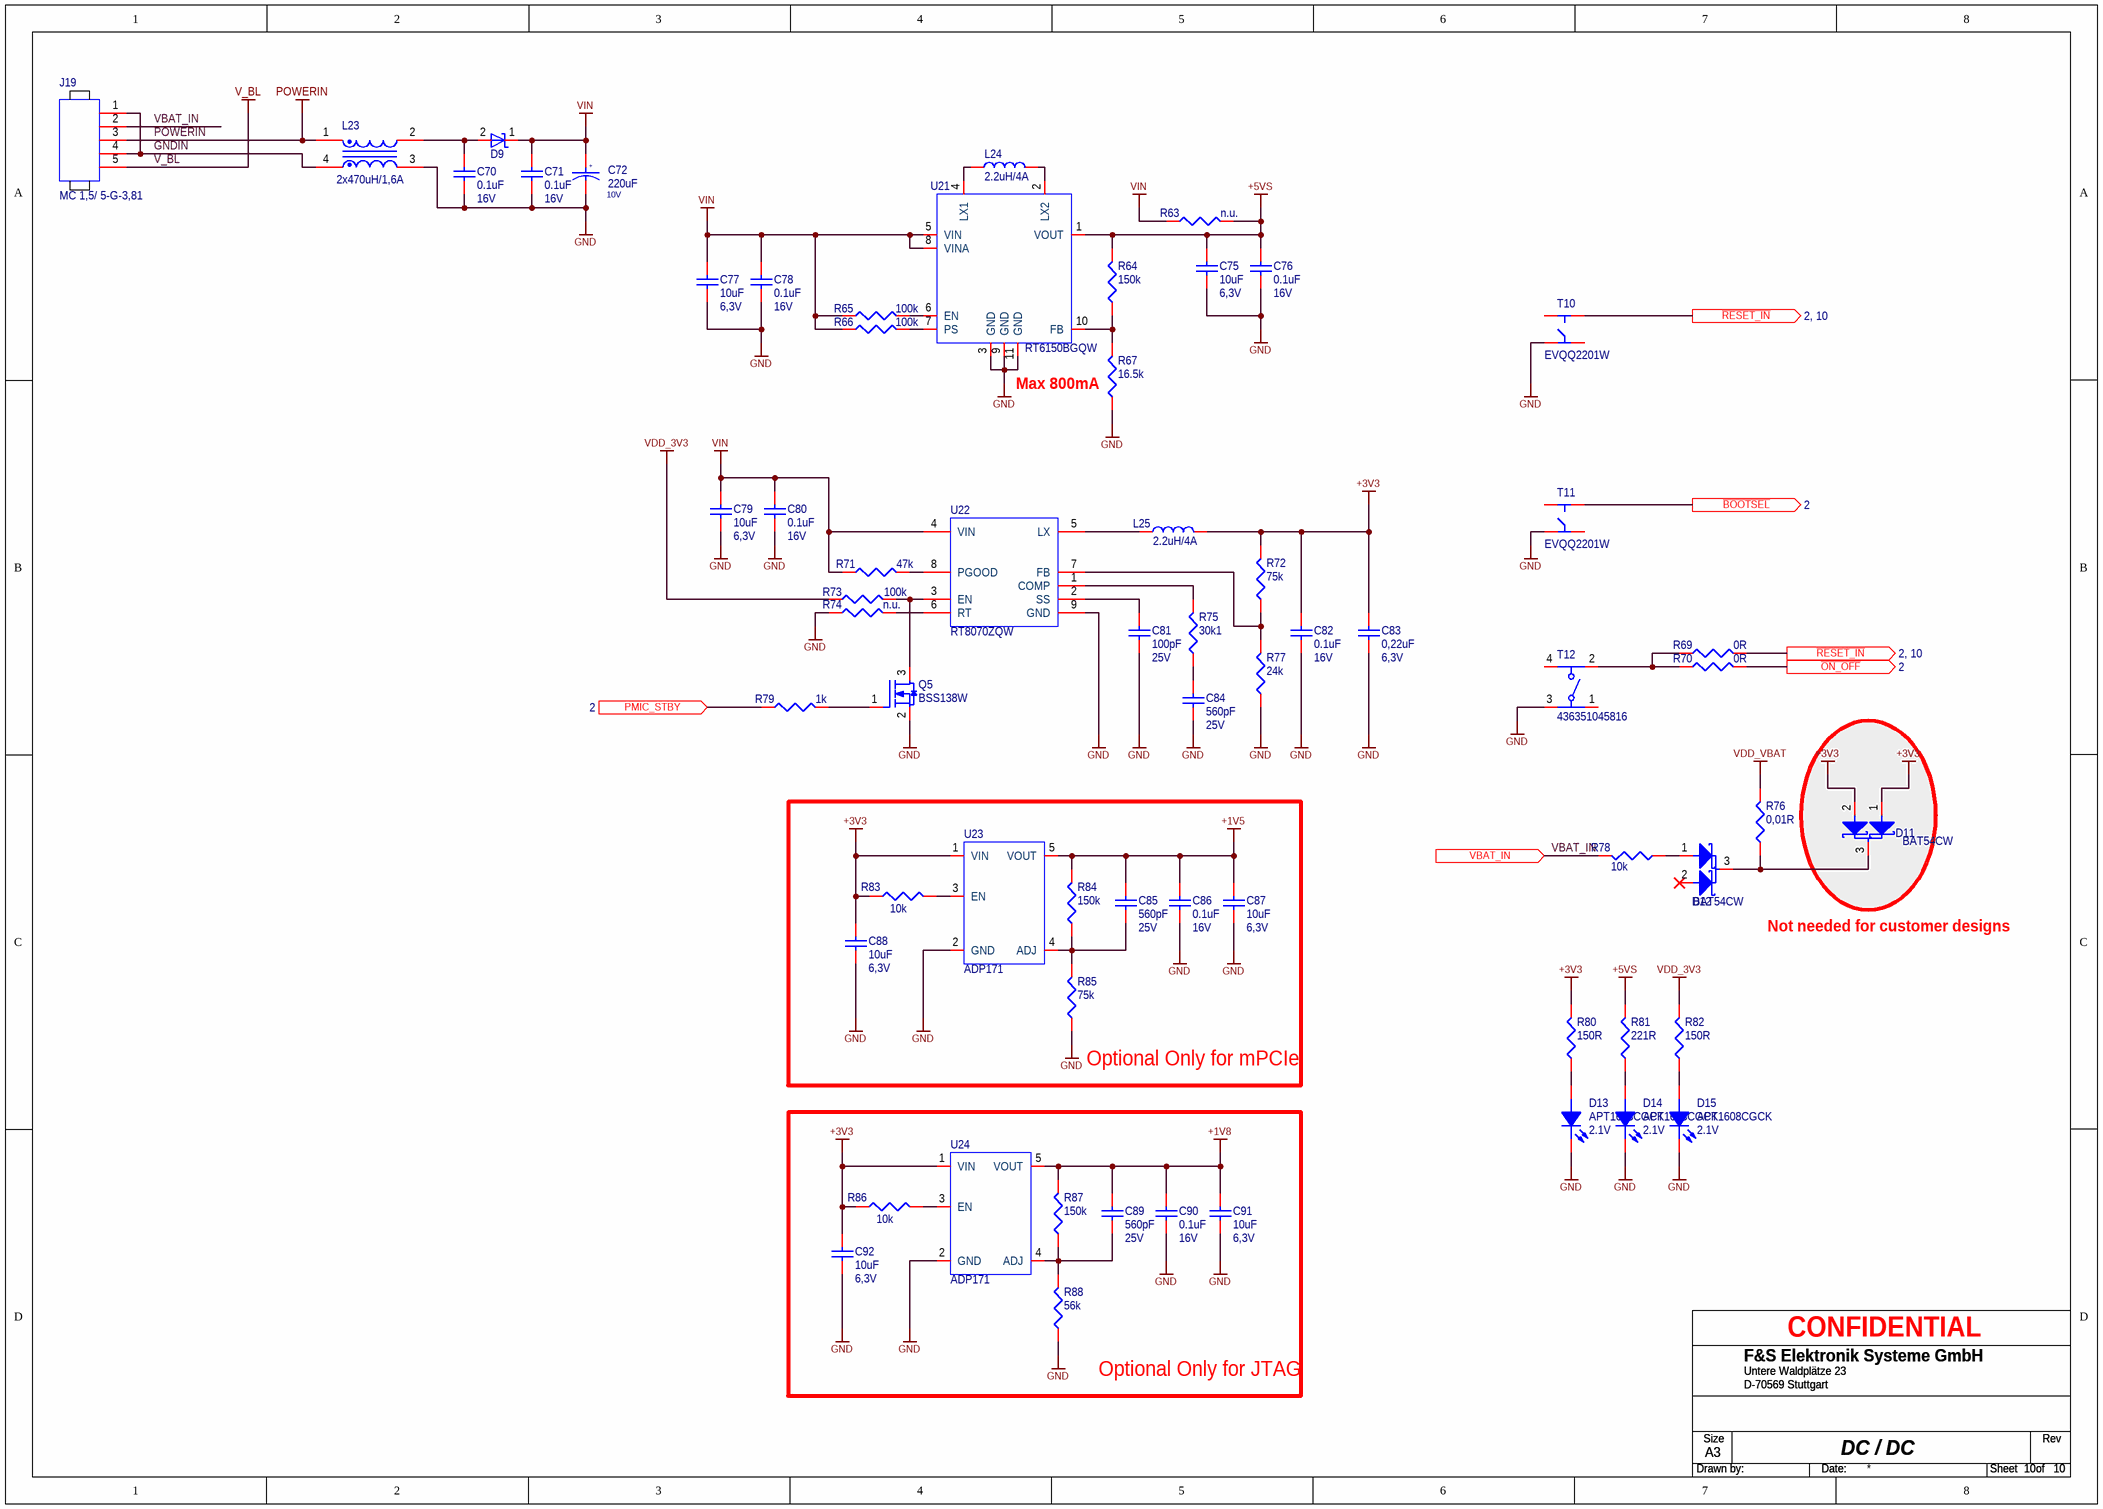
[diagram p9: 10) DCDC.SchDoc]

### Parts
C70  0.1uF  Voltage: 16V  [C0402]
C71  0.1uF  Voltage: 16V  [C0402]
C72  220uF  Voltage: 10V  [C_2312]
C75  10uF  Voltage: 6,3V  [C0603]
C76  0.1uF  Voltage: 16V  [C0402]
C77  10uF  Voltage: 6,3V  [C0603]
C78  0.1uF  Voltage: 16V  [C0402]
C79  10uF  Voltage: 6,3V  [C0603]
C80  0.1uF  Voltage: 16V  [C0402]
C81  100pF  Voltage: 25V  [C0402]
C82  0.1uF  Voltage: 16V  [C0402]
C83  0,22uF  Voltage: 6,3V  [C0805]
C84  560pF  Voltage: 25V  [C0402]
C85  560pF  Voltage: 25V  [C0402]
C86  0.1uF  Voltage: 16V  [C0402]
C87  10uF  Voltage: 6,3V  [C0603]
C88  10uF  Voltage: 6,3V  [C0603]
C89  560pF  Voltage: 25V  [C0402]
C90  0.1uF  Voltage: 16V  [C0402]
C91  10uF  Voltage: 6,3V  [C0603]
C92  10uF  Voltage: 6,3V  [C0603]
D9  SK56L  [DO-214AB]  (value not drawn)
D11  BAT54CW  [SOT323 (SC70)]
D12  BAT54CW  [SOT323 (SC70)]
D13  APT1608CGCK  Voltage: 2.1V  [LED0603]
D14  APT1608CGCK  Voltage: 2.1V  [LED0603]
D15  APT1608CGCK  Voltage: 2.1V  [LED0603]
J19  MC 1,5/ 5-G-3,81  [691322310005]
L23  2x470uH/1,6A  [WE-SL5]
L24  2.2uH/4A  [LD-5X5M-VLC5045]
L25  2.2uH/4A  [LD-5X5M-VLC5045]
Q5  BSS138W  [SOT323 (SC70)]
R63  n.u.  [R0805]
R64  150k  [R0402]
R65  100k  [R0402]
R66  100k  [R0402]
R67  16.5k  [R0402]
R69  0R  [R0402]
R70  0R  [R0402]
R71  47k  [R0402]
R72  75k  [R0402]
R73  100k  [R0402]
R74  n.u.  [R0402]
R75  30k1  [R0402]
R76  0,01R  [R0805]
R77  24k  [R0402]
R78  10k  [R0402]
R79  1k  [R0402]
R80  150R  [R0402]
R81  221R  [R0402]
R82  150R  [R0402]
R83  10k  [R0402]
R84  150k  [R0402]
R85  75k  [R0402]
R86  10k  [R0402]
R87  150k  [R0402]
R88  56k  [R0402]
T10  EVQQ2201W  [EVQQ2 Switch]
T11  EVQQ2201W  [EVQQ2 Switch]
T12  436351045816  [436351045816]
U21  RT6150BGQW  [SON50P250X80_HS-11N]
U22  RT8070ZQW  [WDFN8_0.65P_300X80]
U23  ADP171  [SOT23-5]
U24  ADP171  [SOT23-5]

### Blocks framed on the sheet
Optional Only for mPCIe: C85-C88 R83-R85 U23
Optional Only for JTAG: C89-C92 R86-R88 U24

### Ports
PMIC_STBY (in, see 2), VBAT_IN (in), ~{BOOTSEL} (out, see 2), ~{ON_OFF} (out, see 2), ~{RESET_IN} (out, see 2, 10)

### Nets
+1V5: C85.2 C86.2 C87.2 R84.2 U23.5(VOUT)
+1V8: C89.2 C90.2 C91.2 R87.2 U24.5(VOUT)
+3V3: C82.2 C83.2 C88.2 C92.2 D11.1(ANODE1) D11.2(ANODE2) L25.2 R72.2 R80.2 R83.1 R86.1 U23.1(VIN) U24.1(VIN)
+5VS: C75.2 C76.2 R63.2 R64.2 R81.2 U21.1(VOUT)
GND: C70.1 C71.1 C72.2 C75.1 C76.1 C77.1 C78.1 C79.1 C80.1 C81.1 C82.1 C83.1 C84.1 C86.1 C87.1 C88.1 C90.1 C91.1 C92.1 D13.1(CAT_GRN) D14.1(CAT_GRN) D15.1(CAT_GRN) L23.3 Q5.2 R67.1 R74.1 R77.1 R85.1 R88.1 T10.3 T11.3 T12.3 U21.3(GND) U21.9(GND) U21.11(GND) U22.9(GND) U23.2(GND) U24.2(GND)
POWERIN: J19.3 L23.1
V_BL: J19.5
VDD_3V3: R73.1 R82.2
VDD_VBAT: R76.2
VIN: C71.2 C72.1 C77.2 C78.2 C79.2 C80.2 D9.1(Anode) R63.1 R65.1 R66.1 R71.1 U21.5(VIN) U21.8(VINA) U22.4(VIN)
GNDIN: J19.1 J19.4 L23.4
VBAT_IN: J19.2 R78.2 ; port VBAT_IN
NetC70_2: C70.2 D9.2(Cathode) L23.2
NetC81_2: C81.2 U22.2(SS)
NetC84_2: C84.2 R75.1
NetC85_1: C85.1 R84.1 R85.2 U23.4(ADJ)
NetC89_1: C89.1 R87.1 R88.2 U24.4(ADJ)
NetD1_1: R69.2 T10.2 ; port ~{RESET_IN}
NetD11_3: D11.3(CATHODE) D12.3(CATHODE) R76.1
NetD12_1: D12.1(ANODE1) R78.1
NetD13_2: D13.2(AN_GRN) R80.1
NetD14_2: D14.2(AN_GRN) R81.1
NetD15_2: D15.2(AN_GRN) R82.1
NetJ2_44: R79.1 ; port PMIC_STBY
NetJ2_48: R70.2 ; port ~{ON_OFF}
NetJ2_50: T11.2 ; port ~{BOOTSEL}
NetL24_1: L24.1 U21.4(LX1)
NetL24_2: L24.2 U21.2(LX2)
NetL25_1: L25.1 U22.5(LX)
NetQ5_1: Q5.1 R79.2
NetQ5_3: Q5.3 R73.2 U22.3(EN)
NetR64_1: R64.1 R67.2 U21.10(FB)
NetR65_2: R65.2 U21.6(EN)
NetR66_2: R66.2 U21.7(PS)
NetR69_1: R69.1 R70.1 T12.2
NetR71_2: R71.2 U22.8(PGOOD)
NetR72_1: R72.1 R77.2 U22.7(FB)
NetR74_2: R74.2 U22.6(RT)
NetR75_2: R75.2 U22.1(COMP)
NetR83_2: R83.2 U23.3(EN)
NetR86_2: R86.2 U24.3(EN)

Not connected (* = marked no-connect by the designer): D12 2(ANODE2)*; T10 1 4; T11 1 4; T12 1 4

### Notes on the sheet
- (near R67) Max 800mA
- Not needed for customer designs

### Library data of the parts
C70 C71 C76 C78 C80 C82 C86 C90 = 380: as C44-C46 on sheet 07) LCD CAM
C72 = 718: 220uF  20%  10V  2312  Typ: C; FS-EDV-Nummer: B.CTA.16; Class: Capacitor Tantal; Tolerance: 20; ID: 718
C75 C77 C79 C87 C88 C91 C92 = 406: as C65 on sheet 09) mPCIe
C81 = 387: 100pF  5%  25V  C0G/NP0  0402; FS-EDV-Nummer: B.CKV.68; Class: Capacitor Ceramic; Tolerance: 5; ID: 387
C83 = 439: 0,22uF  10%  6,3V  X7R  0805; FS-EDV-Nummer: B.CKV.62; Class: Capacitor Ceramic; Tolerance: 10; ID: 439
C84 C85 C89 = 388: 560pF  5%  25V  X7R  0402; FS-EDV-Nummer: B.CKV.71; Class: Capacitor Ceramic; Tolerance: 5; ID: 388
D9 = 2696: SK56L-TP  60V  5A  Common Anode  DO-214AB; ID: 2696; Class: DIOD; FS-EDV-Nummer: B.DSCHOT.4
D11 D12 = 2695: BAT54CW  30V  200mA  Dual Common Cathode SOT-323; FS-EDV-Nummer: B.DSCHOT.5; Class: DIOD; ID: 2695
D13-D15 = 2744: as LED1 on sheet 09) mPCIe
J19 = 2729: Stiftl. 5 pol.1 reih. R3,81  liegend; ID: 2729; Class: Connector; FS-EDV-Nummer: B.MST.1R5PS.5; THT: X
L23 = 2697: 2x470uH 1,6A SMD; ID: 2697; FS-EDV-Nummer: B.L.56; Power: 1,6A
L24 L25 = 2741: ID: 2741; FS-EDV-Nummer: B.L.42
Q5 = 2689: as T6 on sheet 07) LCD CAM
R63 = B.R000.2.S: 0R00 0,125W max 5% SMD 0805; Power: 0,125W; Tolerance: 5; ID: 6
R64 R84 R87 = 204: 150k 1/16W 1% SMD 0402; FS-EDV-Nummer: B.R150K.2; Tolerance: 1; ID: 204
R65 R66 R73 = 177: as R49 on sheet 07) LCD CAM
R67 = 303: 16.5k 1/16W 1% SMD 0402; FS-EDV-Nummer: B.R16K5.1; Tolerance: 1; ID: 303
R69 R70 = 173: as R55 on sheet 09) mPCIe
R71 = 186: as R47 on sheet 07) LCD CAM
R72 R85 = 191: 75k 1/16W 1% SMD 0402; FS-EDV-Nummer: B.R75K0.1; Tolerance: 1; ID: 191
R74 = Resistor
R75 = 197: 30k1 1/16W 1% SMD 0402; FS-EDV-Nummer: B.R30K1.1; Tolerance: 1; ID: 197
R76 = 187: 0,01R 1/4W max 5% SMD 0805; FS-EDV-Nummer: B.R0R01.1; Tolerance: 5; ID: 187
R77 = 254: 24k 1/16W 1% SMD 0402; FS-EDV-Nummer: B.R24k0.1; Tolerance: 1; ID: 254
R78 R83 R86 = 170: as R54 on sheet 09) mPCIe
R79 = 166: as R57-R59 on sheet 09) mPCIe
R80 R82 = 172: 150R 1/16W 1% SMD 0402; FS-EDV-Nummer: B.R150R.1; Tolerance: 1; ID: 172
R81 = 174: 221R 1/16W 1% SMD 0402; FS-EDV-Nummer: B.R221R.1; Tolerance: 1; ID: 174
R88 = 326: 56k 1/16W 1% SMD 0402; FS-EDV-Nummer: B.R56K.2; Tolerance: 1; ID: 326
T10 T11 = 2735: Miniatur-Tastschalter Serie EVQ SMD; FS-EDV-Nummer: B.MSW.4; Voltage: 15V; Class: Switch; Power: 20 mA; ID: 2735
T12 = 2736: Tact Switch side push; FS-EDV-Nummer: B.MSW.5; Voltage: 12V; ID: 2736
U21 = 2789: RT6150B DFN10 2.5x2.5mm; ID: 2789; Class: IC; FS-EDV-Nummer: B.ICANA.114
U22 = 1736: RT8070ZQW ADJ 4A Sync WDFN-8 (-40°C bis 85°C); FS-EDV-Nummer: B.ICANA.54; Voltage: max. 5,5V; Class: IC; ID: 1736
U23 U24 = 1740: ADP171AUJZ-R7 ADJ 300mA VIN max. 3,6V TSOT-5 SMD; FS-EDV-Nummer: B.ICANA.58; Voltage: 3,6V; Class: IC; ID: 1740

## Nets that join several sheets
+1V5: 09) mPCIe (J18.6 J18.28 J18.48), 10) DCDC (5 pins)
+1V8: 02) PicoCore B2B (J20.1 R6.2 R7.2), 05) USB3.0 Type-C (C97.2 C98.2 U26.4), 07) LCD CAM (Q7.1 Q8.1 R99.2 R100.2), 10) DCDC (5 pins)
+3V3: 03) USB-HUB (11 pins), 04) USB AUDIO SD (6 pins), 05) USB3.0 Type-C (7 pins), 06) Serial GPIO (12 pins), 07) LCD CAM (10 pins), 08) Ethernet Can (C49.2 R52.1 R53.1 U18.5), 09) mPCIe (14 pins), 10) DCDC (13 pins)
+5VS: 02) PicoCore B2B (J2.41), 03) USB-HUB (C3.2 F3.1 U5.7), 05) USB3.0 Type-C (6 pins), 06) Serial GPIO (F1.1 L9.1), 08) Ethernet Can (C50.1 U18.3), 10) DCDC (6 pins)
GND: 01) Title Page (C2.2 R1.2), 02) PicoCore B2B (48 pins), 03) USB-HUB (30 pins), 04) USB AUDIO SD (18 pins), 05) USB3.0 Type-C (33 pins), 06) Serial GPIO (26 pins), 07) LCD CAM (37 pins), 08) Ethernet Can (10 pins), 09) mPCIe (34 pins), 10) DCDC (38 pins)
GND_SHIELD: 01) Title Page (C1.1 C2.1 R1.1), 03) USB-HUB (J21.9 J21.10 J21.11 J21.12), 05) USB3.0 Type-C (J5.SH1 J5.SH2 J5.SH3 J5.SH4), 08) Ethernet Can (J16.L15 J16.L16 J16.R15 J16.R16)
USB1_OTG_VBUS_F: 02) PicoCore B2B (J2.51), 05) USB3.0 Type-C (5 pins)
V_BL: 07) LCD CAM (J14.1 R61.1 R62.2), 10) DCDC (J19.5)
VCC_COM: 06) Serial GPIO (F1.2 J8.10 J9.10 J10.10), 08) Ethernet Can (J7.1 J7.8)
VDD_3V3: 02) PicoCore B2B (6 pins), 10) DCDC (R73.1 R82.2)
VDD_VBAT: 02) PicoCore B2B (J2.36), 10) DCDC (R76.2)
VIN: 02) PicoCore B2B (R2.2), 07) LCD CAM (5 pins), 10) DCDC (14 pins)
AUDIO_A_GND: 02) PicoCore B2B (J2.4), 04) USB AUDIO SD (12 pins)
CSI_A_CLK_N: 02) PicoCore B2B (J1.76), 07) LCD CAM (J12.8)
CSI_A_CLK_P: 02) PicoCore B2B (J1.74), 07) LCD CAM (J12.9)
CSI_A_DATA0_N: 02) PicoCore B2B (J1.82), 07) LCD CAM (J12.2)
CSI_A_DATA0_P: 02) PicoCore B2B (J1.80), 07) LCD CAM (J12.3)
CSI_A_DATA1_N: 02) PicoCore B2B (J1.88), 07) LCD CAM (J12.5)
CSI_A_DATA1_P: 02) PicoCore B2B (J1.86), 07) LCD CAM (J12.6)
CSI_B_CLK_N: 02) PicoCore B2B (J3.6), 07) LCD CAM (J22.9)
CSI_B_CLK_P: 02) PicoCore B2B (J3.4), 07) LCD CAM (J22.8)
CSI_B_DATA0_N: 02) PicoCore B2B (J3.12), 07) LCD CAM (J22.15)
CSI_B_DATA0_P: 02) PicoCore B2B (J3.10), 07) LCD CAM (J22.14)
CSI_B_DATA1_N: 02) PicoCore B2B (J3.18), 07) LCD CAM (J22.12)
CSI_B_DATA1_P: 02) PicoCore B2B (J3.16), 07) LCD CAM (J22.11)
CSI_B_DATA2_N: 02) PicoCore B2B (J3.24), 07) LCD CAM (J22.6)
CSI_B_DATA2_P: 02) PicoCore B2B (J3.22), 07) LCD CAM (J22.5)
CSI_B_DATA3_N: 02) PicoCore B2B (J3.30), 07) LCD CAM (J22.3)
CSI_B_DATA3_P: 02) PicoCore B2B (J3.28), 07) LCD CAM (J22.2)
DSI_A_CLK_N: 02) PicoCore B2B (J1.19), 07) LCD CAM (L14.4)
DSI_A_CLK_P: 02) PicoCore B2B (J1.17), 07) LCD CAM (L14.1)
DSI_A_DATA0_N: 02) PicoCore B2B (J1.25), 07) LCD CAM (L10.4)
DSI_A_DATA0_P: 02) PicoCore B2B (J1.23), 07) LCD CAM (L10.1)
DSI_A_DATA1_N: 02) PicoCore B2B (J1.31), 07) LCD CAM (L12.4)
DSI_A_DATA1_P: 02) PicoCore B2B (J1.29), 07) LCD CAM (L12.1)
DSI_A_DATA2_N: 02) PicoCore B2B (J1.37), 07) LCD CAM (L13.4)
DSI_A_DATA2_P: 02) PicoCore B2B (J1.35), 07) LCD CAM (L13.1)
DSI_A_DATA3_N: 02) PicoCore B2B (J1.43), 07) LCD CAM (L15.4)
DSI_A_DATA3_P: 02) PicoCore B2B (J1.41), 07) LCD CAM (L15.1)
DSI_B_CLK_N: 02) PicoCore B2B (J1.49), 07) LCD CAM (L20.4)
DSI_B_CLK_P: 02) PicoCore B2B (J1.47), 07) LCD CAM (L20.1)
DSI_B_DATA0_N: 02) PicoCore B2B (J1.55), 07) LCD CAM (L17.4)
DSI_B_DATA0_P: 02) PicoCore B2B (J1.53), 07) LCD CAM (L17.1)
DSI_B_DATA1_N: 02) PicoCore B2B (J1.61), 07) LCD CAM (L18.4)
DSI_B_DATA1_P: 02) PicoCore B2B (J1.59), 07) LCD CAM (L18.1)
DSI_B_DATA2_N: 02) PicoCore B2B (J1.67), 07) LCD CAM (L19.4)
DSI_B_DATA2_P: 02) PicoCore B2B (J1.65), 07) LCD CAM (L19.1)
DSI_B_DATA3_N: 02) PicoCore B2B (J1.73), 07) LCD CAM (L21.4)
DSI_B_DATA3_P: 02) PicoCore B2B (J1.71), 07) LCD CAM (L21.1)
ETH_A_D1_N: 02) PicoCore B2B (J2.3), 08) Ethernet Can (J16.L1)
ETH_A_D1_P: 02) PicoCore B2B (J2.1), 08) Ethernet Can (J16.L2)
ETH_A_D2_N: 02) PicoCore B2B (J2.7), 08) Ethernet Can (J16.L3)
ETH_A_D2_P: 02) PicoCore B2B (J2.5), 08) Ethernet Can (J16.L4)
ETH_A_D3_N: 02) PicoCore B2B (J2.11), 08) Ethernet Can (J16.L5)
ETH_A_D3_P: 02) PicoCore B2B (J2.9), 08) Ethernet Can (J16.L6)
ETH_A_D4_N: 02) PicoCore B2B (J2.15), 08) Ethernet Can (J16.L7)
ETH_A_D4_P: 02) PicoCore B2B (J2.13), 08) Ethernet Can (J16.L8)
ETH_B_D1_N: 02) PicoCore B2B (J2.25), 08) Ethernet Can (J16.R1)
ETH_B_D1_P: 02) PicoCore B2B (J2.23), 08) Ethernet Can (J16.R2)
ETH_B_D2_N: 02) PicoCore B2B (J2.29), 08) Ethernet Can (J16.R3)
ETH_B_D2_P: 02) PicoCore B2B (J2.27), 08) Ethernet Can (J16.R4)
ETH_B_D3_N: 02) PicoCore B2B (J2.33), 08) Ethernet Can (J16.R5)
ETH_B_D3_P: 02) PicoCore B2B (J2.31), 08) Ethernet Can (J16.R6)
ETH_B_D4_N: 02) PicoCore B2B (J2.37), 08) Ethernet Can (J16.R7)
ETH_B_D4_P: 02) PicoCore B2B (J2.35), 08) Ethernet Can (J16.R8)
GPIO_J1_44: 02) PicoCore B2B (J1.44), 07) LCD CAM (J12.11)
GPIO_J1_46: 02) PicoCore B2B (J1.46), 05) USB3.0 Type-C (R103.2)
I2C_B_SCL: 02) PicoCore B2B (J1.3 R8.2), 07) LCD CAM (J12.13 J13.27 J15.3 Q7.3)
I2C_B_SDA: 02) PicoCore B2B (J1.5 R9.2), 07) LCD CAM (J12.14 J13.25 J15.2 Q8.3)
I2S_B_RXFS: 02) PicoCore B2B (J2.77 TP27.1), 05) USB3.0 Type-C (R102.2)
~{I2C_B_IRQ}: 02) PicoCore B2B (J1.1 R5.2), 07) LCD CAM (J13.26 J15.5)
MPCIE_CLK_N: 02) PicoCore B2B (J1.91), 09) mPCIe (J18.11)
MPCIE_CLK_P: 02) PicoCore B2B (J1.89), 09) mPCIe (J18.13)
MPCIE_CRX_N: 02) PicoCore B2B (J1.85), 09) mPCIe (J18.23)
MPCIE_CRX_P: 02) PicoCore B2B (J1.83), 09) mPCIe (J18.25)
MPCIE_CTX_N: 02) PicoCore B2B (J1.79), 09) mPCIe (J18.31)
MPCIE_CTX_P: 02) PicoCore B2B (J1.77), 09) mPCIe (J18.33)
NetC20_2: 02) PicoCore B2B (J2.64), 04) USB AUDIO SD (C20.2 J6.5 U7.3)
NetC26_1: 02) PicoCore B2B (J2.18), 04) USB AUDIO SD (C26.1)
NetC27_1: 02) PicoCore B2B (J2.20), 04) USB AUDIO SD (C27.1)
NetC29_2: 02) PicoCore B2B (J2.10), 04) USB AUDIO SD (C29.2 L7.2), 06) Serial GPIO (J11.41)
NetC30_2: 02) PicoCore B2B (J2.2), 04) USB AUDIO SD (C30.2 U9.5)
NetC48_2: 02) PicoCore B2B (J2.14), 06) Serial GPIO (C48.2)
NetC51_1: 02) PicoCore B2B (J2.8), 06) Serial GPIO (C51.1)
NetC52_2: 02) PicoCore B2B (J2.12), 06) Serial GPIO (C52.2)
NetC67_1: 02) PicoCore B2B (J2.6), 06) Serial GPIO (C67.1)
NetD1_1: 02) PicoCore B2B (D1.1 J2.42 Q2.1), 10) DCDC (R69.2 T10.2)
NetD3_3: 02) PicoCore B2B (J2.56), 04) USB AUDIO SD (D3.3)
NetJ1_2: 02) PicoCore B2B (J1.2), 07) LCD CAM (J15.4)
NetJ1_4: 02) PicoCore B2B (J1.4), 06) Serial GPIO (J11.16)
NetJ1_6: 02) PicoCore B2B (J1.6), 06) Serial GPIO (J11.17)
NetJ1_7: 02) PicoCore B2B (J1.7), 07) LCD CAM (J13.28)
NetJ1_9: 02) PicoCore B2B (J1.9), 07) LCD CAM (R68.1)
NetJ1_10: 02) PicoCore B2B (J1.10), 06) Serial GPIO (J11.24), 08) Ethernet Can (U18.4)
NetJ1_11: 02) PicoCore B2B (J1.11), 07) LCD CAM (R104.1)
NetJ1_12: 02) PicoCore B2B (J1.12), 06) Serial GPIO (J11.26), 08) Ethernet Can (U18.1)
NetJ1_13: 02) PicoCore B2B (J1.13), 07) LCD CAM (R48.1)
NetJ1_14: 02) PicoCore B2B (J1.14), 06) Serial GPIO (J11.36)
NetJ1_16: 02) PicoCore B2B (J1.16), 06) Serial GPIO (J11.38)
NetJ1_18: 02) PicoCore B2B (J1.18), 06) Serial GPIO (U10.9)
NetJ1_20: 02) PicoCore B2B (J1.20), 06) Serial GPIO (U10.10)
NetJ1_22: 02) PicoCore B2B (J1.22), 06) Serial GPIO (R39.1 R41.1)
NetJ1_24: 02) PicoCore B2B (J1.24), 06) Serial GPIO (R40.1 R42.1)
NetJ1_26: 02) PicoCore B2B (J1.26), 06) Serial GPIO (U11.9)
NetJ1_28: 02) PicoCore B2B (J1.28), 06) Serial GPIO (U11.20)
NetJ1_30: 02) PicoCore B2B (J1.30), 06) Serial GPIO (U10.12)
NetJ1_32: 02) PicoCore B2B (J1.32), 06) Serial GPIO (U10.11)
NetJ1_34: 02) PicoCore B2B (J1.34), 06) Serial GPIO (J11.15)
NetJ1_36: 02) PicoCore B2B (J1.36), 06) Serial GPIO (J11.13)
NetJ1_40: 02) PicoCore B2B (J1.40), 09) mPCIe (R55.2)
NetJ1_42: 02) PicoCore B2B (J1.42), 09) mPCIe (R56.2)
NetJ1_48: 02) PicoCore B2B (J1.48), 05) USB3.0 Type-C (U30.8)
NetJ1_50: 02) PicoCore B2B (J1.50), 05) USB3.0 Type-C (U30.7)
NetJ1_52: 02) PicoCore B2B (J1.52), 06) Serial GPIO (J11.18)
NetJ1_54: 02) PicoCore B2B (J1.54), 06) Serial GPIO (J11.8)
NetJ1_56: 02) PicoCore B2B (J1.56), 06) Serial GPIO (J11.4)
NetJ1_58: 02) PicoCore B2B (J1.58), 06) Serial GPIO (J11.5)
NetJ1_60: 02) PicoCore B2B (J1.60), 06) Serial GPIO (J11.6)
NetJ1_62: 02) PicoCore B2B (J1.62), 06) Serial GPIO (J11.3)
NetJ1_64: 02) PicoCore B2B (J1.64), 06) Serial GPIO (J23.5)
NetJ1_66: 02) PicoCore B2B (J1.66), 06) Serial GPIO (J23.4)
NetJ1_68: 02) PicoCore B2B (J1.68), 06) Serial GPIO (J23.3)
NetJ1_70: 02) PicoCore B2B (J1.70), 06) Serial GPIO (J23.2)
NetJ1_95: 02) PicoCore B2B (J1.95), 09) mPCIe (J18.22)
NetJ1_97: 02) PicoCore B2B (J1.97), 09) mPCIe (J18.1)
NetJ2_17: 02) PicoCore B2B (J2.17), 08) Ethernet Can (J16.L14)
NetJ2_21: 02) PicoCore B2B (J2.21), 08) Ethernet Can (J16.R14)
NetJ2_22: 02) PicoCore B2B (J2.22), 04) USB AUDIO SD (TP1.1)
NetJ2_44: 02) PicoCore B2B (J2.44), 10) DCDC (R79.1)
NetJ2_47: 02) PicoCore B2B (J2.47), 03) USB-HUB (U6.27)
NetJ2_48: 02) PicoCore B2B (J2.48), 10) DCDC (R70.2)
NetJ2_50: 02) PicoCore B2B (J2.50), 10) DCDC (T11.2)
NetJ2_52: 02) PicoCore B2B (J2.52), 04) USB AUDIO SD (R23.2 R24.2 R29.2)
NetJ2_58: 02) PicoCore B2B (J2.58), 04) USB AUDIO SD (R22.1)
NetJ2_60: 02) PicoCore B2B (J2.60), 04) USB AUDIO SD (R21.1 T1.3)
NetJ2_62: 02) PicoCore B2B (J2.62), 04) USB AUDIO SD (J6.3 R24.1 U7.4)
NetJ2_63: 02) PicoCore B2B (J2.63), 06) Serial GPIO (J11.34)
NetJ2_65: 02) PicoCore B2B (J2.65), 06) Serial GPIO (J11.10)
NetJ2_66: 02) PicoCore B2B (J2.66), 04) USB AUDIO SD (J6.7 R23.1 U8.6)
NetJ2_67: 02) PicoCore B2B (J2.67), 06) Serial GPIO (J11.12)
NetJ2_68: 02) PicoCore B2B (J2.68), 04) USB AUDIO SD (J6.8 U8.1)
NetJ2_69: 02) PicoCore B2B (J2.69), 06) Serial GPIO (J11.14)
NetJ2_70: 02) PicoCore B2B (J2.70), 04) USB AUDIO SD (J6.1 U8.4)
NetJ2_72: 02) PicoCore B2B (J2.72), 04) USB AUDIO SD (J6.2 U8.3)
NetJ2_73: 02) PicoCore B2B (J2.73), 06) Serial GPIO (J11.7)
NetJ2_74: 02) PicoCore B2B (J2.74), 06) Serial GPIO (J11.19)
NetJ2_75: 02) PicoCore B2B (J2.75), 06) Serial GPIO (J11.9)
NetJ2_76: 02) PicoCore B2B (J2.76), 06) Serial GPIO (J11.20)
NetJ2_78: 02) PicoCore B2B (J2.78), 06) Serial GPIO (J11.21)
NetJ2_80: 02) PicoCore B2B (J2.80), 06) Serial GPIO (J11.22)
NetJ2_84: 02) PicoCore B2B (J2.84), 06) Serial GPIO (J11.35)
NetJ2_86: 02) PicoCore B2B (J2.86), 06) Serial GPIO (J11.33)
NetJ2_88: 02) PicoCore B2B (J2.88), 06) Serial GPIO (J11.32)
NetJ2_90: 02) PicoCore B2B (J2.90), 06) Serial GPIO (J11.31)
NetJ2_92: 02) PicoCore B2B (J2.92), 06) Serial GPIO (J11.30)
NetJ2_94: 02) PicoCore B2B (J2.94), 06) Serial GPIO (J11.29)
NetJ2_96: 02) PicoCore B2B (J2.96), 06) Serial GPIO (J11.28)
NetJ2_98: 02) PicoCore B2B (J2.98), 06) Serial GPIO (J11.25)
NetJ2_100: 02) PicoCore B2B (J2.100), 06) Serial GPIO (J11.23)
NetJ3_13: 02) PicoCore B2B (J3.13), 05) USB3.0 Type-C (R60.2 R95.2)
NetJ3_15: 02) PicoCore B2B (J3.15), 05) USB3.0 Type-C (R98.1 R102.1 R103.1 U30.10)
NetJ3_17: 02) PicoCore B2B (J3.17), 05) USB3.0 Type-C (R96.2 U26.12)
NetJ18_20: 06) Serial GPIO (R45.1), 09) mPCIe (J18.20)
NetQ1_3: 02) PicoCore B2B (Q1.3 R4.1), 03) USB-HUB (R10.1)
USB1_RX_N: 02) PicoCore B2B (J3.23), 05) USB3.0 Type-C (U26.14)
USB1_RX_P: 02) PicoCore B2B (J3.21), 05) USB3.0 Type-C (U26.13)
USB1_TX_N: 02) PicoCore B2B (J3.29), 05) USB3.0 Type-C (U26.9)
USB1_TX_P: 02) PicoCore B2B (J3.27), 05) USB3.0 Type-C (U26.10)
USB_OTG_D_N: 02) PicoCore B2B (J2.59), 05) USB3.0 Type-C (U25.C5)
USB_OTG_D_P: 02) PicoCore B2B (J2.57), 05) USB3.0 Type-C (U25.C6)
USBD_N: 02) PicoCore B2B (J2.45), 03) USB-HUB (U6.30)
USBD_P: 02) PicoCore B2B (J2.43), 03) USB-HUB (U6.31)
USBDM3_N: 03) USB-HUB (U6.6), 09) mPCIe (L22.2)
USBDM3_P: 03) USB-HUB (U6.7), 09) mPCIe (L22.3)

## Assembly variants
FERT1S: not fitted C93 C94 C95 C96 C97 C98 C106 D11 J3 J7 J8 J9 J10 J11 J16 J19 J21 J22 J24 Q7 Q8 R6 R7 R41 R42 R60 R61 R63 R70 R74 R93 R95 R96 R99 R100 R101 R103 TP11 TP12 TP13 TP14 U26 U27
FERT1B: not fitted A-REF1 A-REF2 A-REF3 A-REF4 A-REF5 A-REF6 C1 C2 C3 C4 C5 C6 C7 C8 C9 C10 C11 C12 C13 C14 C15 C16 C17 C18 C19 C20 C21 C22 C23 C24 C25 C26 C27 C28 C29 C30 C31 C32 C33 C34 C35 C36 C37 C38 C39 C40 C41 C42 C43 C44 C45 C46 C47 C48 C49 C50 C51 C52 C53 C54 C55 C56 C57 C58 C59 C60 C61 C62 C63 C64 C65 C66 C67 C68 C69 C70 C71 C72 C75 C76 C77 C78 C79 C80 C81 C82 C83 C84 C85 C86 C87 C88 C89 C90 C91 C92 C93 C94 C95 C96 C97 C98 C99 C100 C101 C102 C103 C104 C105 C106 D1 D2 D3 D4 D5 D6 D7 D8 D9 D11 D12 D13 D14 D15 F1 F2 F3 J1 J2 J3 J4 J5 J6 J12 J13 J14 J15 J17 J18 J20 J22 J23 L1 L2 L3 L4 L5 L6 L7 L8 L9 L10 L11 L12 L13 L14 L15 L16 L17 L18 L19 L20 L21 L22 L23 L24 L25 LABEL1 LED1 LED2 LED3 M1 PCB1 Q1 Q2 Q3 Q5 Q6 Q7 Q8 R1 R2 R3 R4 R5 R6 R7 R8 R9 R10 R11 R12 R13 R14 R15 R16 R17 R18 R19 R20 R21 R22 R23 R24 R25 R26 R27 R28 R29 R30 R31 R32 R33 R34 R35 R36 R37 R38 R39 R40 R41 R42 R43 R44 R45 R46 R47 R48 R49 R50 R51 R52 R53 R54 R55 R56 R57 R58 R59 R60 R61 R62 R63 R64 R65 R66 R67 R68 R69 R70 R71 R72 R73 R74 R75 R76 R77 R78 R79 R80 R81 R82 R83 R84 R85 R86 R87 R88 R89 R90 R91 R92 R93 R94 R95 R96 R97 R98 R99 R100 R101 R102 R103 R104 SP1 SP2 SW1 T1 T2 T3 T4 T5 T6 T10 T11 T12 TP1 TP2 TP3 TP4 TP5 TP6 TP7 TP8 TP9 TP10 U1 U2 U3 U4 U5 U6 U7 U8 U9 U10 U11 U12 U13 U14 U15 U16 U18 U21 U22 U23 U24 U25 U26 U27 U28 U29 U30 Y1
FERT2S: not fitted D11 J7 J8 J9 J10 J11 J16 J19 J21 J24 L11 R6 R7 R41 R42 R61 R63 R70 R74 R93 R101 R102 R103
FERT2B: not fitted A-REF1 A-REF2 A-REF3 A-REF4 A-REF5 A-REF6 C1 C2 C3 C4 C5 C6 C7 C8 C9 C10 C11 C12 C13 C14 C15 C16 C17 C18 C19 C20 C21 C22 C23 C24 C25 C26 C27 C28 C29 C30 C31 C32 C33 C34 C35 C36 C37 C38 C39 C40 C41 C42 C43 C44 C45 C46 C47 C48 C49 C50 C51 C52 C53 C54 C55 C56 C57 C58 C59 C60 C61 C62 C63 C64 C65 C66 C67 C68 C69 C70 C71 C72 C75 C76 C77 C78 C79 C80 C81 C82 C83 C84 C85 C86 C87 C88 C89 C90 C91 C92 C93 C94 C95 C96 C97 C98 C99 C100 C101 C102 C103 C104 C105 C106 D1 D2 D3 D4 D5 D6 D7 D8 D9 D11 D12 D13 D14 D15 F1 F2 F3 J1 J2 J3 J4 J5 J6 J12 J13 J14 J15 J17 J18 J20 J22 J23 L1 L2 L3 L4 L5 L6 L7 L8 L9 L10 L11 L12 L13 L14 L15 L16 L17 L18 L19 L20 L21 L22 L23 L24 L25 LABEL1 LED1 LED2 LED3 M1 PCB1 Q1 Q2 Q3 Q5 Q6 Q7 Q8 R1 R2 R3 R4 R5 R6 R7 R8 R9 R10 R11 R12 R13 R14 R15 R16 R17 R18 R19 R20 R21 R22 R23 R24 R25 R26 R27 R28 R29 R30 R31 R32 R33 R34 R35 R36 R37 R38 R39 R40 R41 R42 R43 R44 R45 R46 R47 R48 R49 R50 R51 R52 R53 R54 R55 R56 R57 R58 R59 R60 R61 R62 R63 R64 R65 R66 R67 R68 R69 R70 R71 R72 R73 R74 R75 R76 R77 R78 R79 R80 R81 R82 R83 R84 R85 R86 R87 R88 R89 R90 R91 R92 R93 R94 R95 R96 R97 R98 R99 R100 R101 R102 R103 R104 SP1 SP2 SW1 T1 T2 T3 T4 T5 T6 T10 T11 T12 TP1 TP2 TP3 TP4 TP5 TP6 TP7 TP8 TP9 TP10 U1 U2 U3 U4 U5 U6 U7 U8 U9 U10 U11 U12 U13 U14 U15 U16 U18 U21 U22 U23 U24 U25 U26 U27 U28 U29 U30 Y1
FERT3B: not fitted A-REF1 A-REF2 A-REF3 A-REF4 A-REF5 A-REF6 C1 C2 C3 C4 C5 C6 C7 C8 C9 C10 C11 C12 C13 C14 C15 C16 C17 C18 C19 C20 C21 C22 C23 C24 C25 C26 C27 C28 C29 C30 C31 C32 C33 C34 C35 C36 C37 C38 C39 C40 C41 C42 C43 C44 C45 C46 C47 C48 C49 C50 C51 C52 C53 C54 C55 C56 C57 C58 C59 C60 C61 C62 C63 C64 C65 C66 C67 C68 C69 C70 C71 C72 C75 C76 C77 C78 C79 C80 C81 C82 C83 C84 C85 C86 C87 C88 C89 C90 C91 C92 C93 C94 C95 C96 C97 C98 C99 C100 C101 C102 C103 C104 C105 C106 D1 D2 D3 D4 D5 D6 D7 D8 D9 D11 D12 D13 D14 D15 F1 F2 F3 J1 J2 J3 J4 J5 J6 J12 J13 J14 J15 J17 J18 J20 J22 J23 L1 L2 L3 L4 L5 L6 L7 L8 L9 L10 L11 L12 L13 L14 L15 L16 L17 L18 L19 L20 L21 L22 L23 L24 L25 LABEL1 LED1 LED2 LED3 M1 PCB1 Q1 Q2 Q3 Q5 Q6 Q7 Q8 R1 R2 R3 R4 R5 R6 R7 R8 R9 R10 R11 R12 R13 R14 R15 R16 R17 R18 R19 R20 R21 R22 R23 R24 R25 R26 R27 R28 R29 R30 R31 R32 R33 R34 R35 R36 R37 R38 R39 R40 R41 R42 R43 R44 R45 R46 R47 R48 R49 R50 R51 R52 R53 R54 R55 R56 R57 R58 R59 R60 R61 R62 R63 R64 R65 R66 R67 R68 R69 R70 R71 R72 R73 R74 R75 R76 R77 R78 R79 R80 R81 R82 R83 R84 R85 R86 R87 R88 R89 R90 R91 R92 R93 R94 R95 R96 R97 R98 R99 R100 R101 R102 R103 R104 SP1 SP2 SW1 T1 T2 T3 T4 T5 T6 T10 T11 T12 TP1 TP2 TP3 TP4 TP5 TP6 TP7 TP8 TP9 TP10 U1 U2 U3 U4 U5 U6 U7 U8 U9 U10 U11 U12 U13 U14 U15 U16 U18 U21 U22 U23 U24 U25 U26 U27 U28 U29 U30 Y1
FERT4S: not fitted C93 C94 C95 C96 C97 C98 C106 D11 J3 J7 J8 J9 J10 J11 J16 J19 J21 J22 J24 Q7 Q8 R6 R7 R21 R41 R42 R60 R61 R63 R70 R74 R93 R95 R96 R99 R100 R101 R103 TP11 TP12 TP13 TP14 U26 U27
FERT4B: not fitted A-REF1 A-REF2 A-REF3 A-REF4 A-REF5 A-REF6 C1 C2 C3 C4 C5 C6 C7 C8 C9 C10 C11 C12 C13 C14 C15 C16 C17 C18 C19 C20 C21 C22 C23 C24 C25 C26 C27 C28 C29 C30 C31 C32 C33 C34 C35 C36 C37 C38 C39 C40 C41 C42 C43 C44 C45 C46 C47 C48 C49 C50 C51 C52 C53 C54 C55 C56 C57 C58 C59 C60 C61 C62 C63 C64 C65 C66 C67 C68 C69 C70 C71 C72 C75 C76 C77 C78 C79 C80 C81 C82 C83 C84 C85 C86 C87 C88 C89 C90 C91 C92 C93 C94 C95 C96 C97 C98 C99 C100 C101 C102 C103 C104 C105 C106 D1 D2 D3 D4 D5 D6 D7 D8 D9 D11 D12 D13 D14 D15 F1 F2 F3 J1 J2 J3 J4 J5 J6 J12 J13 J14 J15 J17 J18 J20 J22 J23 L1 L2 L3 L4 L5 L6 L7 L8 L9 L10 L11 L12 L13 L14 L15 L16 L17 L18 L19 L20 L21 L22 L23 L24 L25 LABEL1 LED1 LED2 LED3 M1 PCB1 Q1 Q2 Q3 Q5 Q6 Q7 Q8 R1 R2 R3 R4 R5 R6 R7 R8 R9 R10 R11 R12 R13 R14 R15 R16 R17 R18 R19 R20 R21 R22 R23 R24 R25 R26 R27 R28 R29 R30 R31 R32 R33 R34 R35 R36 R37 R38 R39 R40 R41 R42 R43 R44 R45 R46 R47 R48 R49 R50 R51 R52 R53 R54 R55 R56 R57 R58 R59 R60 R61 R62 R63 R64 R65 R66 R67 R68 R69 R70 R71 R72 R73 R74 R75 R76 R77 R78 R79 R80 R81 R82 R83 R84 R85 R86 R87 R88 R89 R90 R91 R92 R93 R94 R95 R96 R97 R98 R99 R100 R101 R102 R103 R104 SP1 SP2 SW1 T1 T2 T3 T4 T5 T6 T10 T11 T12 TP1 TP2 TP3 TP4 TP5 TP6 TP7 TP8 TP9 TP10 U1 U2 U3 U4 U5 U6 U7 U8 U9 U10 U11 U12 U13 U14 U15 U16 U18 U21 U22 U23 U24 U25 U26 U27 U28 U29 U30 Y1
